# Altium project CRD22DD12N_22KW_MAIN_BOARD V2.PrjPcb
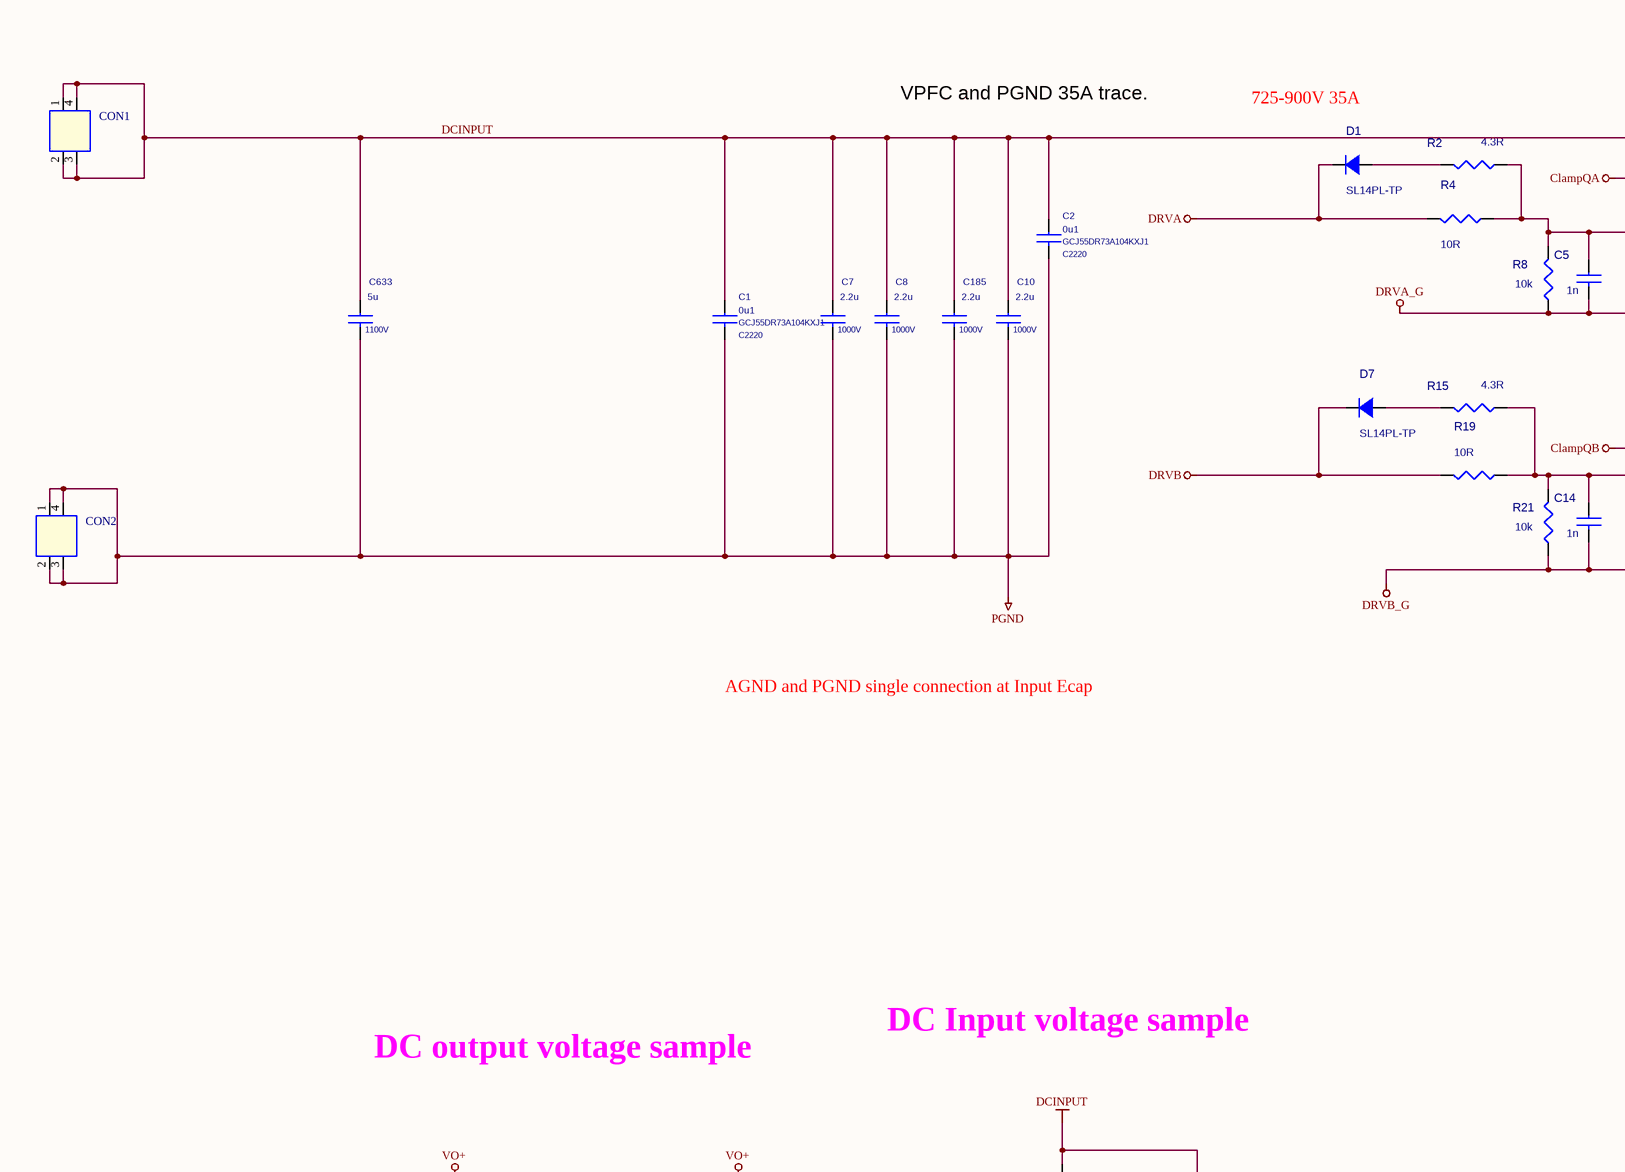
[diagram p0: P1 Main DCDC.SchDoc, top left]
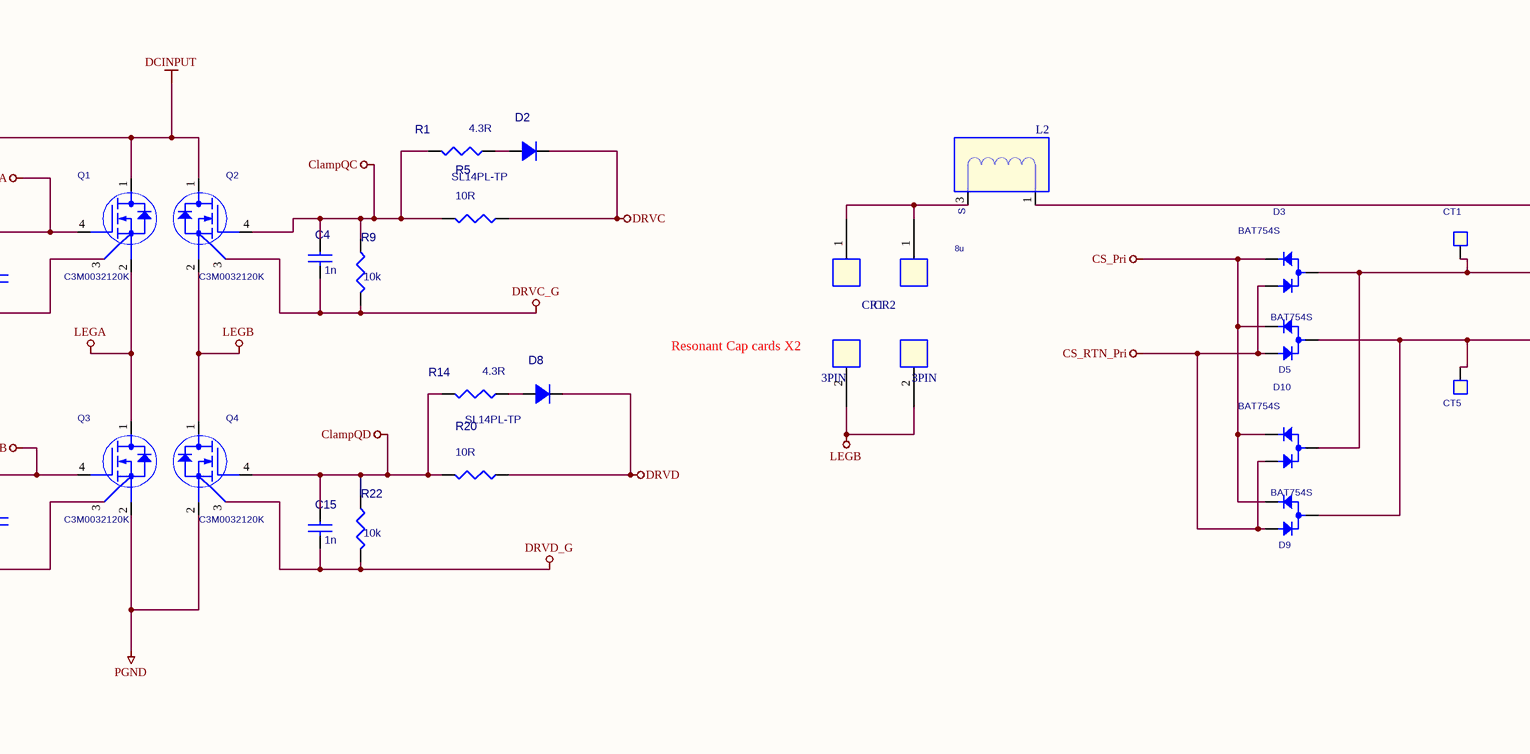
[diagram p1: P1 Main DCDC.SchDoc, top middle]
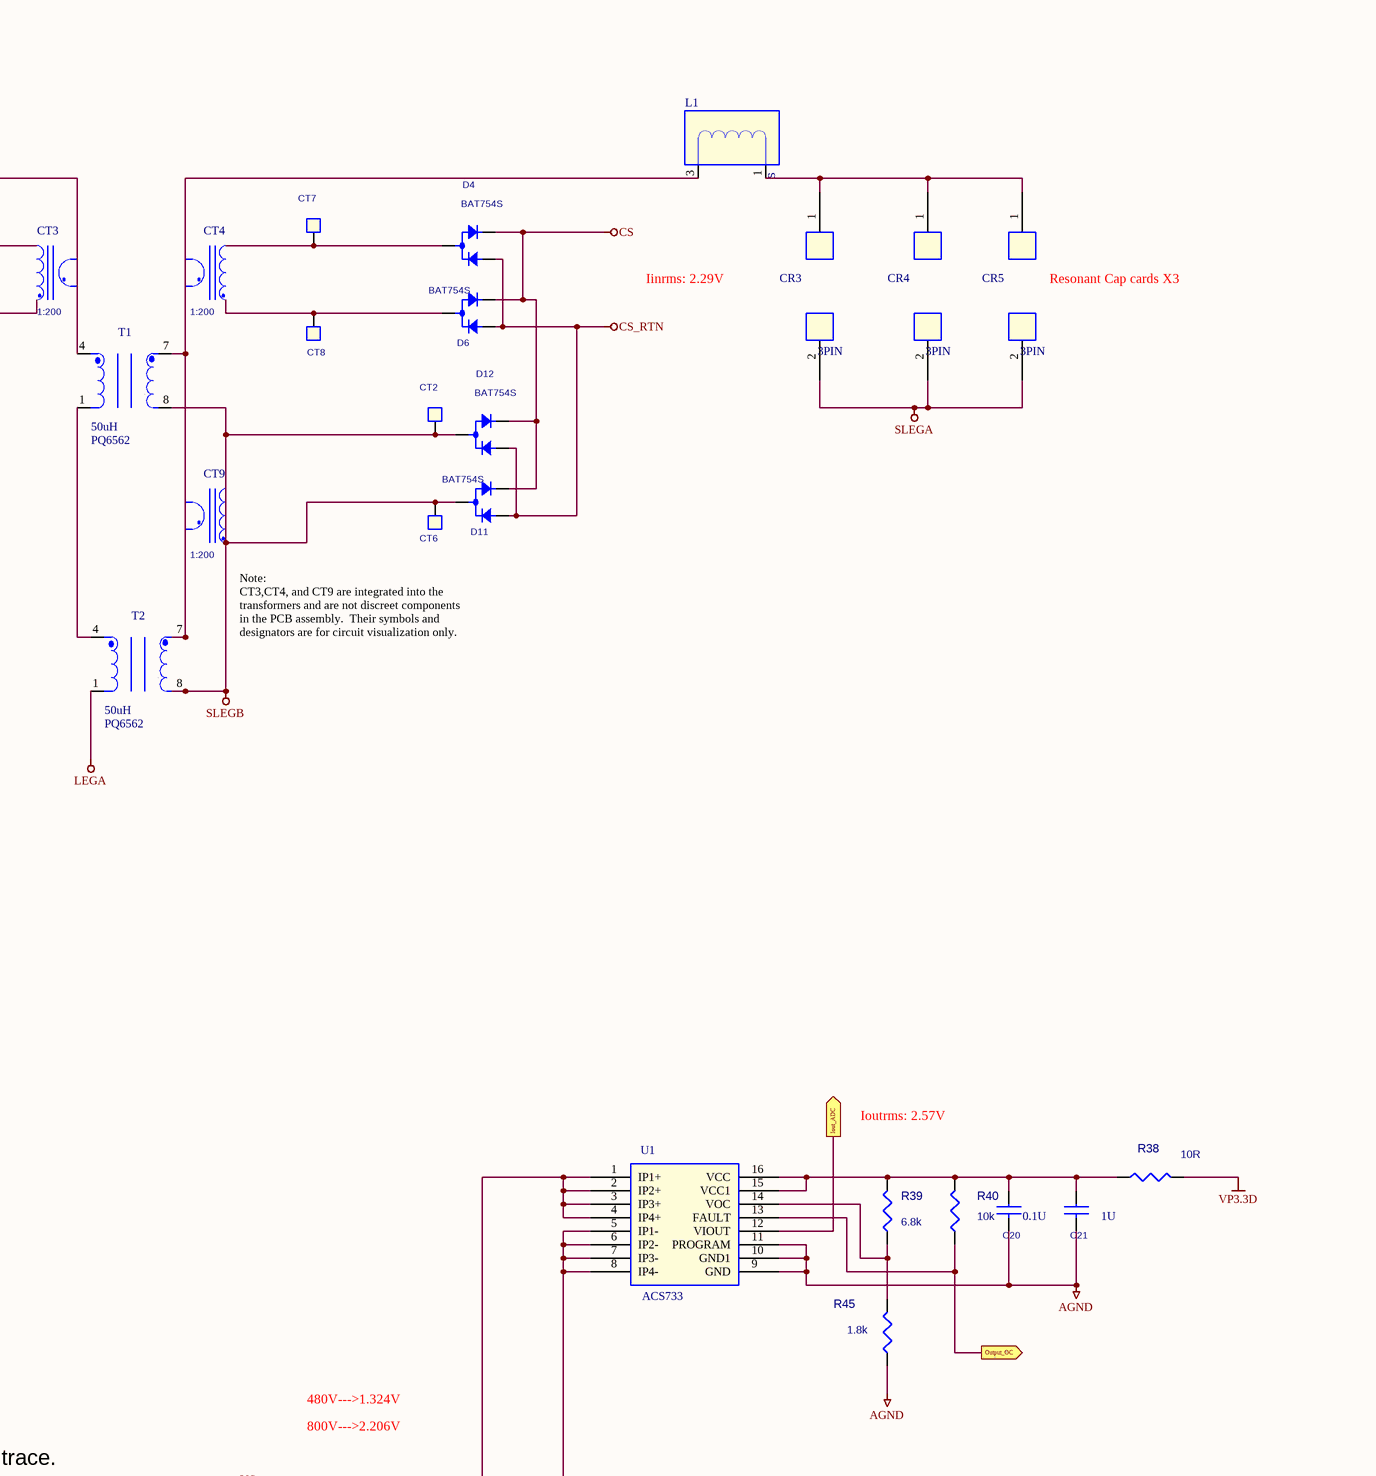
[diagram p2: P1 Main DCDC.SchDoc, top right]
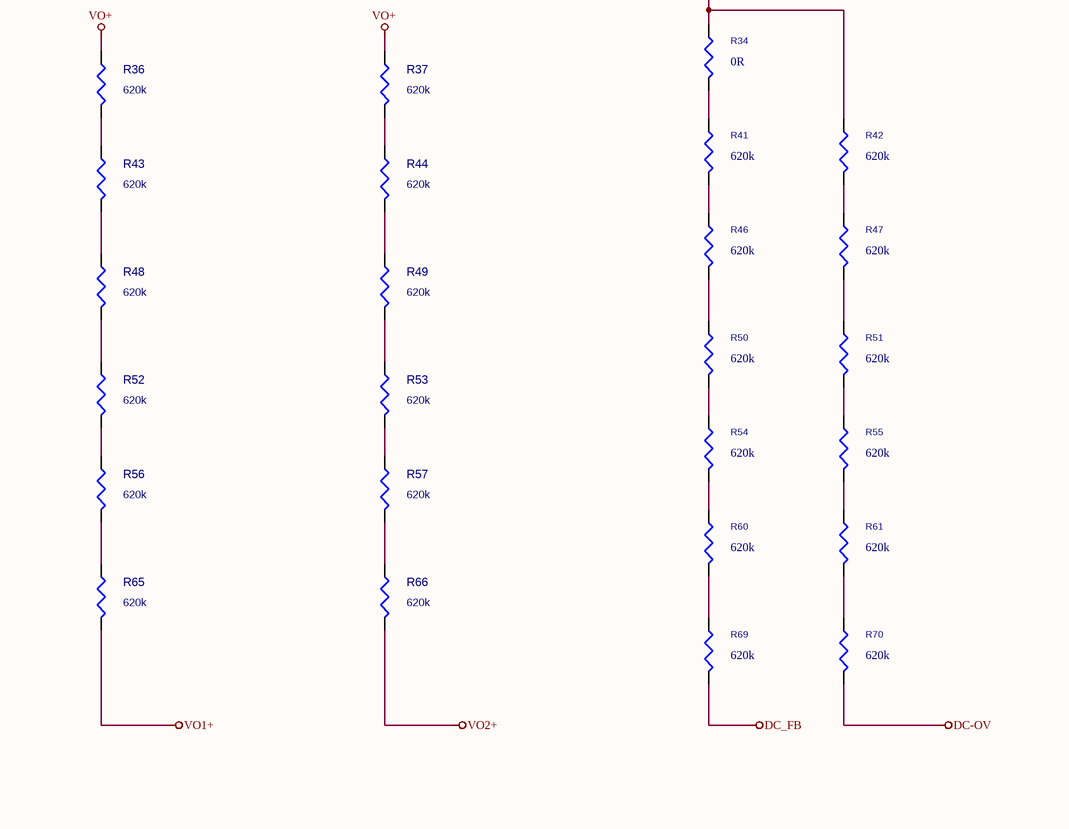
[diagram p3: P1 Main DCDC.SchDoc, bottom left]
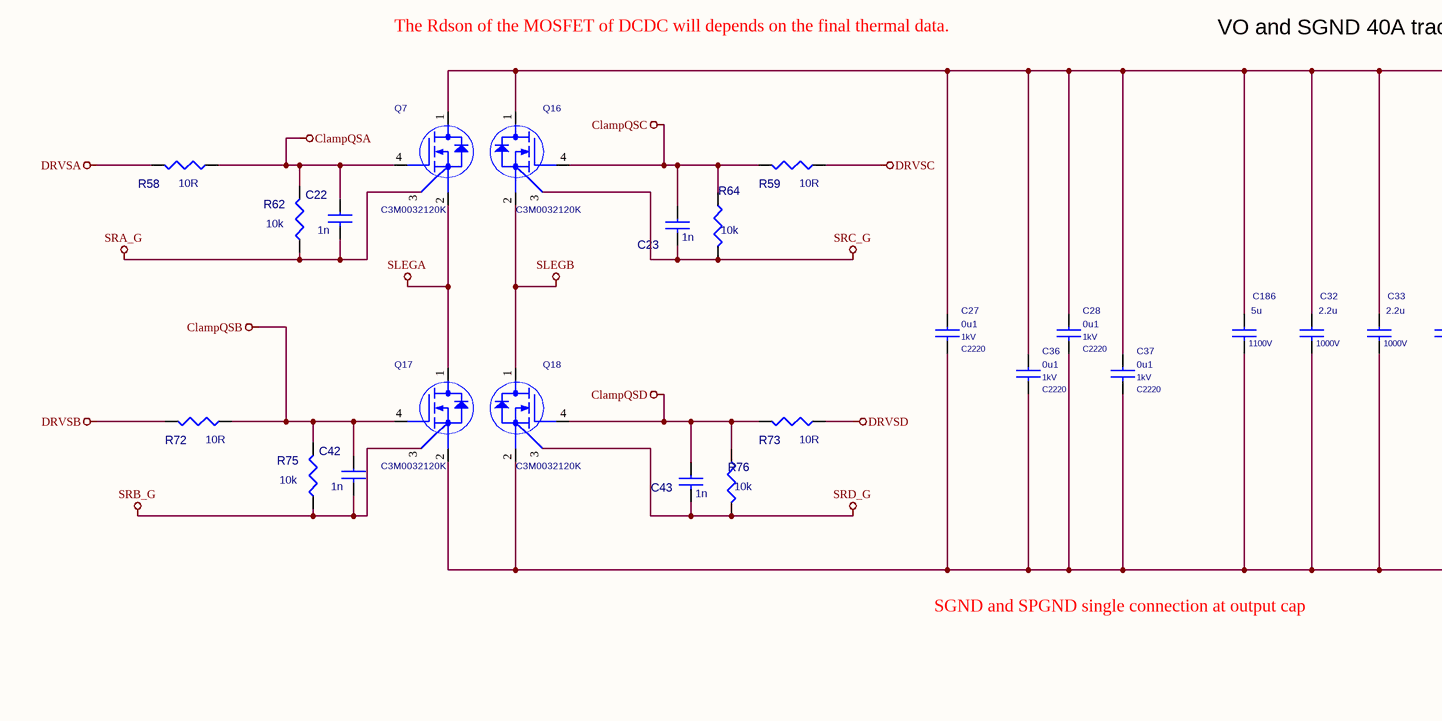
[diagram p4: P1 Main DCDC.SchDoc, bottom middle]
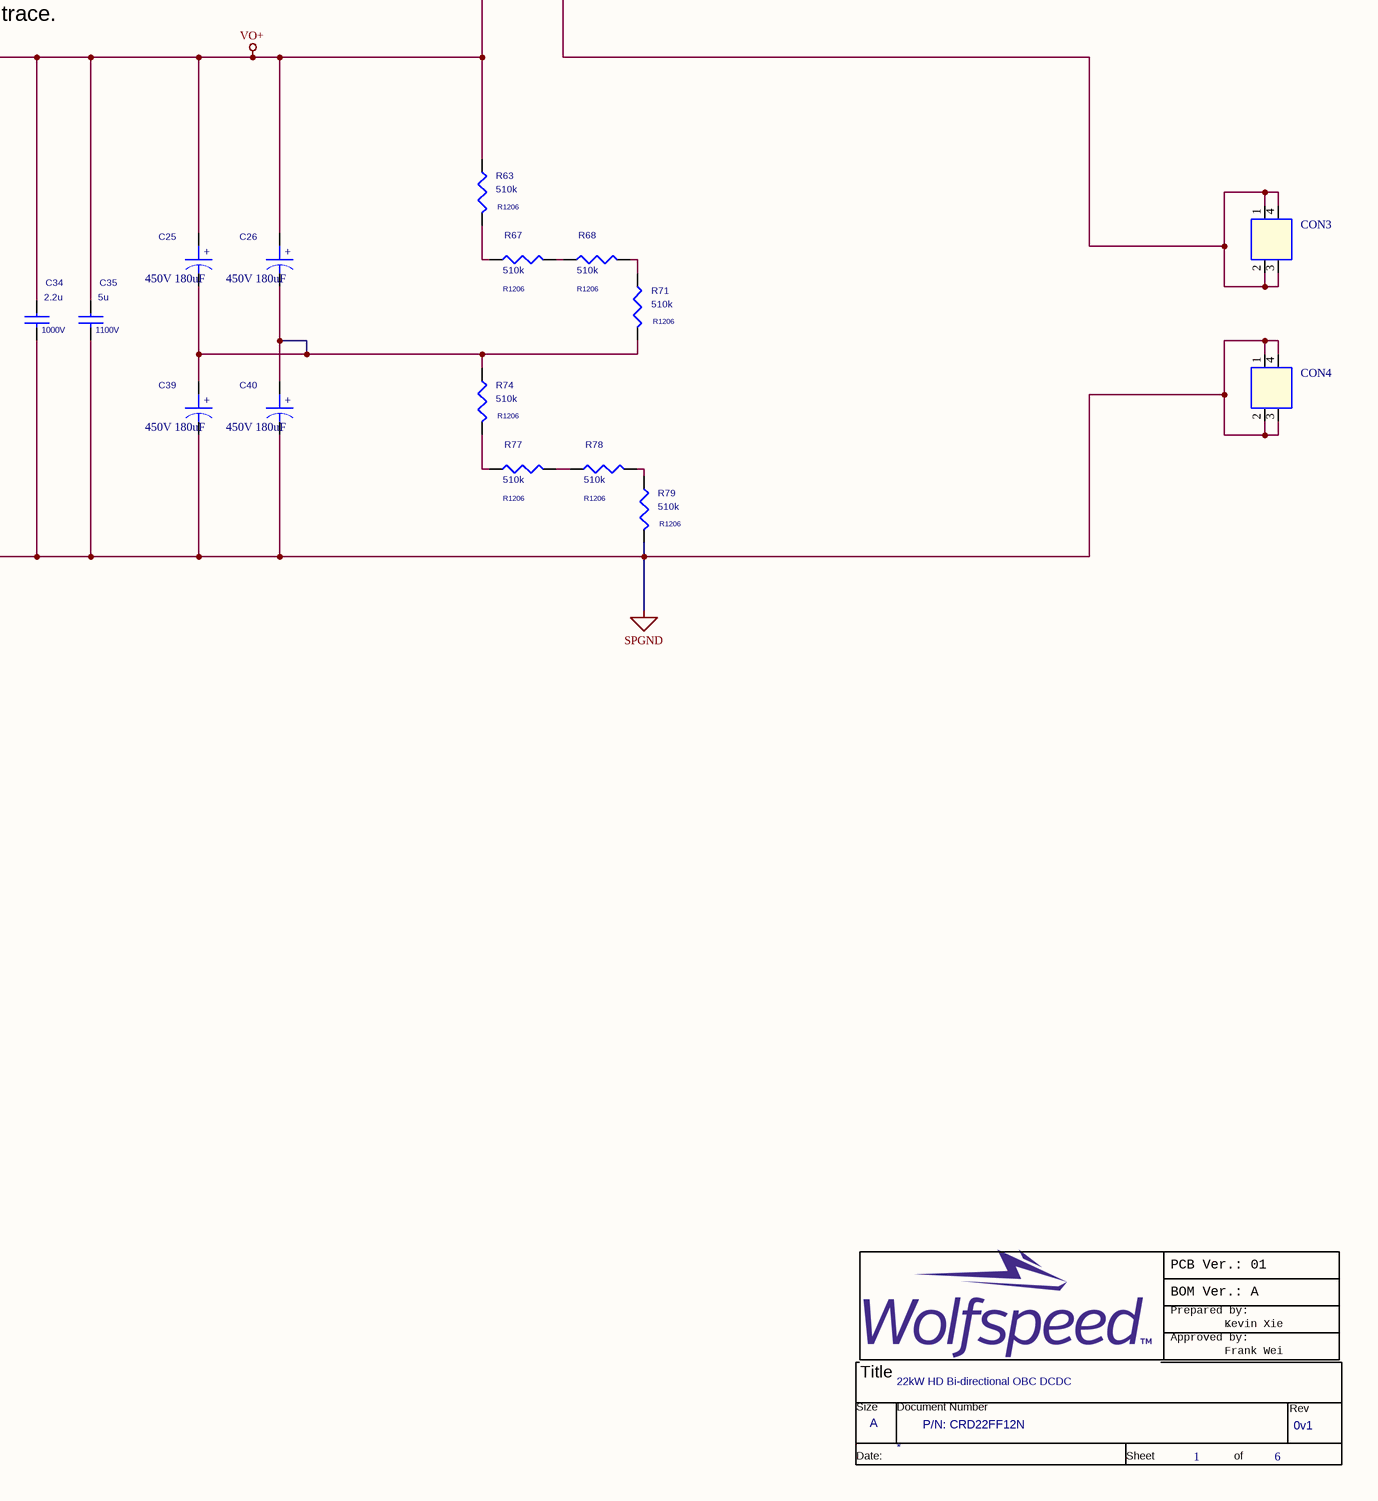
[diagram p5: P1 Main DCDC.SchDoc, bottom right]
5 sheets, 347 parts. Net scope: flat (ports and power ports of the same name join across sheets).
Board file: CRD22DD12N_22KW_BI-OBC_main_BOARD_DCDC_V2.PcbDoc
Sheets:
  P1 Main DCDC.SchDoc
  P2 Bias POWER SUPPLY.SchDoc
  P3 Isolation Interface.SchDoc
  P4 DCDC Primary Gate Dr.SchDoc
  P5 DCDC Secondary Gate .SchDoc

## Sheet P1 Main DCDC.SchDoc
size 840 x 594 mm

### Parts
(Parts that share a designator on the sheet are numbered #1, #2 ... from top to bottom, then left to right.)
*#1  Page Count: 6  Page Number: 1  Page Size: A  Title: 22kW HD Bi-directional OBC DCDC  RevCode: 0v1  Doc: P/N: CRD22FF12N  (hidden comment: TitleBlock0_cree_power)  (graphical)
C1  0u1  value1: GCJ55DR73A104KXJ1  [C2220]
C2  0u1  value1: GCJ55DR73A104KXJ1  [C2220]
C4  1n  [C0603]
C5  1n  [C0603]
C7  2.2u  value1: 1000V  [capfilm_31_5x12_5mm]
C8  2.2u  value1: 1000V  [capfilm_31_5x12_5mm]
C10  2.2u  value1: 1000V  [capfilm_31_5x12_5mm]
C14  1n  [C0603]
C15  1n  [C0603]
C20  0.1U  [C0603]
C21  1U  [C0603]
C22  1n  [C0603]
C23  1n  [C0603]
C25  450V 180uF  [ecap_d18p7_5]
C26  450V 180uF  [ecap_d18p7_5]
C27  0u1  value1: 1kV  [C2220]
C28  0u1  value1: 1kV  [C2220]
C32  2.2u  value1: 1000V  [capfilm_31_5x12_5mm]
C33  2.2u  value1: 1000V  [capfilm_31_5x12_5mm]
C34  2.2u  value1: 1000V  [capfilm_31_5x12_5mm]
C35  5u  value1: 1100V  [capfilm_31_5x18_5mm]
C36  0u1  value1: 1kV  [C2220]
C37  0u1  value1: 1kV  [C2220]
C39  450V 180uF  [ecap_d18p7_5]
C40  450V 180uF  [ecap_d18p7_5]
C42  1n  [C0603]
C43  1n  [C0603]
C185  2.2u  value1: 1000V  [capfilm_31_5x12_5mm]
C186  5u  value1: 1100V  [capfilm_31_5x18_5mm]
C633  5u  value1: 1100V  [capfilm_31_5x18_5mm]
CON1  Connecter  [thread4_9p9x5_1110x920]  (value not drawn)
CON2  Connecter  [thread4_9p9x5_1110x920]  (value not drawn)
CON3  Connecter  [thread4_9p9x5_1110x920]  (value not drawn)
CON4  Connecter  [thread4_9p9x5_1110x920]  (value not drawn)
CR1  3PIN  [Crb]
CR2  3PIN  [Crb]
CR3  3PIN  [Crb]
CR4  3PIN  [Crb]
CR5  3PIN  [Crb]
CT1  T1T2  [TH47_CR98]  (value not drawn)
CT2  T1T2  [TH47_CR98]  (value not drawn)
CT3  1:200  [NO]
CT4  1:200  [NO]
CT5  T1T2  [TH47_CR98]  (value not drawn)
CT6  T1T2  [TH47_CR98]  (value not drawn)
CT7  T1T2  [TH47_CR98]  (value not drawn)
CT8  T1T2  [TH47_CR98]  (value not drawn)
CT9  1:200  [NO]
D1  SL14PL-TP  [SOD-123]
D2  SL14PL-TP  [SOD-123]
D3  BAT754S  [SOT-23]
D4  BAT754S  [SOT-23]
D5  BAT754S  [SOT-23]
D6  BAT754S  [SOT-23]
D7  SL14PL-TP  [SOD-123]
D8  SL14PL-TP  [SOD-123]
D9  BAT754S  [SOT-23]
D10  BAT754S  [SOT-23]
D11  BAT754S  [SOT-23]
D12  BAT754S  [SOT-23]
L1  8u  [l6]  (value not drawn)
L2  8u  [l6]
Q1  C3M0032120K  [to-247-4l]
Q2  C3M0032120K  [to-247-4l]
Q3  C3M0032120K  [to-247-4l]
Q4  C3M0032120K  [to-247-4l]
Q7  C3M0032120K  [to-247-4l]
Q16  C3M0032120K  [to-247-4l]
Q17  C3M0032120K  [to-247-4l]
Q18  C3M0032120K  [to-247-4l]
R1  4.3R  [R1206]
R2  4.3R  [R1206]
R4  10R  [R1206]
R5  10R  [R1206]
R8  10k  [R0603]
R9  10k  [R0603]
R14  4.3R  [R1206]
R15  4.3R  [R1206]
R19  10R  [R1206]
R20  10R  [R1206]
R21  10k  [R0603]
R22  10k  [R0603]
R34  0R  [R1206]
R36  620k  [R1206]
R37  620k  [R1206]
R38  10R  [R0603]
R39  6.8k  [R0603]
R40  10k  [R0603]
R41  620k  [R1206]
R42  620k  [R1206]
R43  620k  [R1206]
R44  620k  [R1206]
R45  1.8k  [R0603]
R46  620k  [R1206]
R47  620k  [R1206]
R48  620k  [R1206]
R49  620k  [R1206]
R50  620k  [R1206]
R51  620k  [R1206]
R52  620k  [R1206]
R53  620k  [R1206]
R54  620k  [R1206]
R55  620k  [R1206]
R56  620k  [R1206]
R57  620k  [R1206]
R58  10R  [R1206]
R59  10R  [R1206]
R60  620k  [R1206]
R61  620k  [R1206]
R62  10k  [R0603]
R63  510k  [R1206]
R64  10k  [R0603]
R65  620k  [R1206]
R66  620k  [R1206]
R67  510k  [R1206]
R68  510k  [R1206]
R69  620k  [R1206]
R70  620k  [R1206]
R71  510k  [R1206]
R72  10R  [R1206]
R73  10R  [R1206]
R74  510k  [R1206]
R75  10k  [R0603]
R76  10k  [R0603]
R77  510k  [R1206]
R78  510k  [R1206]
R79  510k  [R1206]
T1  50uH  LLF Part Number: PQ6562  [IND-LET0234-34x17]
T2  50uH  LLF Part Number: PQ6562  [IND-LET0234-34x17]
U1  ACS733  [SOICW-16]

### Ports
Iout_ADC (out), Output_OC (out)

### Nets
AGND: C20.2 C21.2 R45.2 U1.9(GND) U1.10(GND1) U1.11(PROGRAM)
ClampQA: C5.1 Q1.4(G) R2.1 R4.1 R8.2
ClampQB: C14.1 Q3.4(G) R15.1 R19.1 R21.2
ClampQC: C4.1 Q2.4(G) R1.2 R5.2 R9.2
ClampQD: C15.1 Q4.4(G) R14.2 R20.2 R22.2
ClampQSA: C22.1 Q7.4(G) R58.1 R62.2
ClampQSB: C42.1 Q17.4(G) R72.1 R75.2
ClampQSC: C23.1 Q16.4(G) R59.2 R64.2
ClampQSD: C43.1 Q18.4(G) R73.2 R76.2
CS: D4.2(C2) D6.2(C2) D11.2(C2) D12.2(C2)
CS_Pri: D3.2(C2) D5.2(C2) D9.2(C2) D10.2(C2)
CS_RTN: D4.1(C1) D6.1(C1) D11.1(C1) D12.1(C1)
CS_RTN_Pri: D3.1(C1) D5.1(C1) D9.1(C1) D10.1(C1)
DC-OV: R70.1
DC_FB: R69.1
DCINPUT: C1.1 C2.1 C7.1 C8.1 C10.1 C185.1 C633.1 CON1.1 CON1.2 CON1.3 CON1.4 Q1.1(D) Q2.1(D) R34.2 R42.2
DRVA: D1.2(K) R4.2
DRVA_G: C5.2 Q1.3(GS) R8.1
DRVB: D7.2(K) R19.2
DRVB_G: C14.2 Q3.3(GS) R21.1
DRVC: D2.2(K) R5.1
DRVC_G: C4.2 Q2.3(GS) R9.1
DRVD: D8.2(K) R20.1
DRVD_G: C15.2 Q4.3(GS) R22.1
DRVSA: R58.2
DRVSB: R72.2
DRVSC: R59.1
DRVSD: R73.1
LEGA: Q1.2(S) Q3.1(D) T2.1
LEGB: CR1.2 CR2.2 Q2.2(S) Q4.1(D)
PGND: C1.2 C2.2 C7.2 C8.2 C10.2 C185.2 C633.2 CON2.1 CON2.2 CON2.3 CON2.4 Q3.2(S) Q4.2(S)
SLEGA: CR3.2 CR4.2 CR5.2 Q7.2(S) Q17.1(D)
SLEGB: CT2.1 CT6.1 D11.3(A) D12.3(A) Q16.2(S) Q18.1(D) T1.8 T2.8
SPGND: C27.2 C28.2 C32.2 C33.2 C34.2 C35.2 C36.2 C37.2 C39.2 C40.2 C186.2 CON4.1 CON4.2 CON4.3 CON4.4 Q17.2(S) Q18.2(S) R79.2
SRA_G: C22.2 Q7.3(GS) R62.1
SRB_G: C42.2 Q17.3(GS) R75.1
SRC_G: C23.2 Q16.3(GS) R64.1
SRD_G: C43.2 Q18.3(GS) R76.1
VO1+: R65.2
VO2+: R66.2
VO+: C25.1 C26.1 C27.1 C28.1 C32.1 C33.1 C34.1 C35.1 C36.1 C37.1 C186.1 Q7.1(D) Q16.1(D) R36.1 R37.1 R63.1 U1.1(IP1+) U1.2(IP2+) U1.3(IP3+) U1.4(IP4+)
VP3.3D: R38.1
NetC20_1: C20.1 C21.1 R38.2 R39.1 R40.1 U1.15(VCC1) U1.16(VCC)
NetC25_2: C25.2 C26.2 C39.1 C40.1 R71.2 R74.1
NetCON3_1: CON3.1 CON3.2 CON3.3 CON3.4 U1.5(IP1-) U1.6(IP2-) U1.7(IP3-) U1.8(IP4-)
NetCR1_1: CR1.1 CR2.1 L2.3
NetCR3_1: CR3.1 CR4.1 CR5.1 L1.1
NetCT1_1: CT1.1 D3.3(A) D10.3(A)
NetCT5_1: CT5.1 D5.3(A) D9.3(A)
NetCT7_1: CT7.1 D4.3(A)
NetCT8_1: CT8.1 D6.3(A)
NetD1_1: D1.1(A) R2.2
NetD2_1: D2.1(A) R1.1
NetD7_1: D7.1(A) R15.2
NetD8_1: D8.1(A) R14.1
NetJ1_14: U1.12(VIOUT) ; port Iout_ADC
NetJ1_16: R40.2 U1.13(FAULT) ; port Output_OC
NetL1_3: L1.3 T1.7 T2.7
NetL2_1: L2.1 T1.4
NetR34_1: R34.1 R41.2
NetR36_2: R36.2 R43.1
NetR37_2: R37.2 R44.1
NetR39_2: R39.2 R45.1 U1.14(VOC)
NetR41_1: R41.1 R46.2
NetR42_1: R42.1 R47.2
NetR43_2: R43.2 R48.1
NetR44_2: R44.2 R49.1
NetR46_1: R46.1 R50.2
NetR47_1: R47.1 R51.2
NetR48_2: R48.2 R52.1
NetR49_2: R49.2 R53.1
NetR50_1: R50.1 R54.2
NetR51_1: R51.1 R55.2
NetR52_2: R52.2 R56.1
NetR53_2: R53.2 R57.1
NetR54_1: R54.1 R60.2
NetR55_1: R55.1 R61.2
NetR56_2: R56.2 R65.1
NetR57_2: R57.2 R66.1
NetR60_1: R60.1 R69.2
NetR61_1: R61.1 R70.2
NetR63_2: R63.2 R67.1
NetR67_2: R67.2 R68.1
NetR68_2: R68.2 R71.1
NetR74_2: R74.2 R77.1
NetR77_2: R77.2 R78.1
NetR78_2: R78.2 R79.1
NetT1_1: T1.1 T2.4

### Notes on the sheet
- VPFC and PGND 35A trace.
- 725-900V 35A
- Iinrms: 2.29V
- (near CR5) Resonant Cap cards X3
- (near CR1) Resonant Cap cards X2
- AGND and PGND single connection at Input Ecap
- (near CT9) Note:
  CT3,CT4, and CT9 are integrated into the transformers and are not discreet components in the PCB assembly.  Their symbols and designators are for circuit visualization only.
- DC output voltage sample
- DC Input voltage sample
- Ioutrms: 2.57V
- The Rdson of the MOSFET of DCDC will depends on the final thermal data.
- 480V--->1.324V
- 800V--->2.206V
- VO and SGND 40A trace.
- SGND and SPGND single connection at output cap
- PCB Ver.: 01
- BOM Ver.: A
- Prepared by:
- Approved by:
- .
- Frank Wei
- Kevin Xie

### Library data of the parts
C1 C2 C4 C5 C7 C8 C10 C14 C15 C22 C23 C27 C28 C32-C37 C42 C43 C185 C186 C633 = CAP NP_Dup1
C20 C21 = CAP NP
C25 C26 C39 C40 = CAP POL
CT1 CT2 CT5-CT8 = CON1_2
CT3 CT4 CT9 = TRNSFMR 29398_4
D1 D2 D7 D8 = DIODE_0
D3-D6 D9-D12 = FMMD6100/SOT_0
L1 = 126LNS_1
L2 = 126LNS_5
Q1-Q4 Q7 Q16-Q18 = C3M0065090J_4
R1 R2 R4 R5 R8 R9 R14 R15 R19-R22 R36-R40 R43-R45 R48 R49 R52 R53 R56-R59 R62 R64-R66 R72 R73 R75 R76 = R
R34 R41 R42 R46 R47 R50 R51 R54 R55 R60 R61 R69 R70 = RESISTOR
R63 R67 R68 R71 R74 R77-R79 = RESISTOR_Dup1
T1 = LET0234_326uH_0: PCB Footprint: XFMR-PQ6562_T1
T2 = LET0234_326uH_0: PCB Footprint: XFMR-PQ6562_T2
U1 = MCR1101_0

## Sheet P2 Bias POWER SUPPLY.SchDoc
size 840 x 594 mm
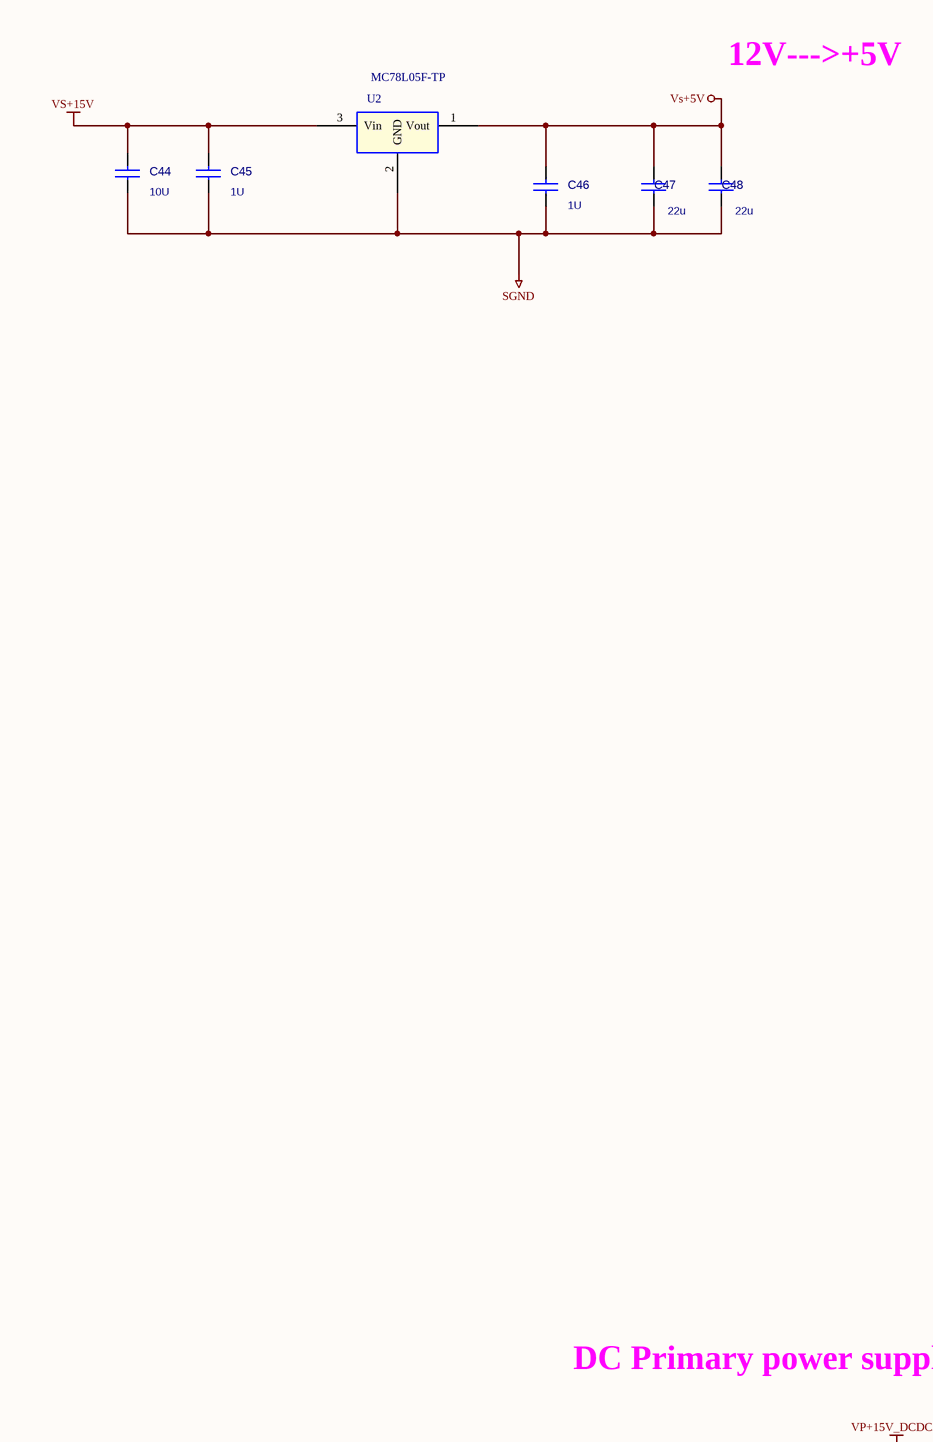
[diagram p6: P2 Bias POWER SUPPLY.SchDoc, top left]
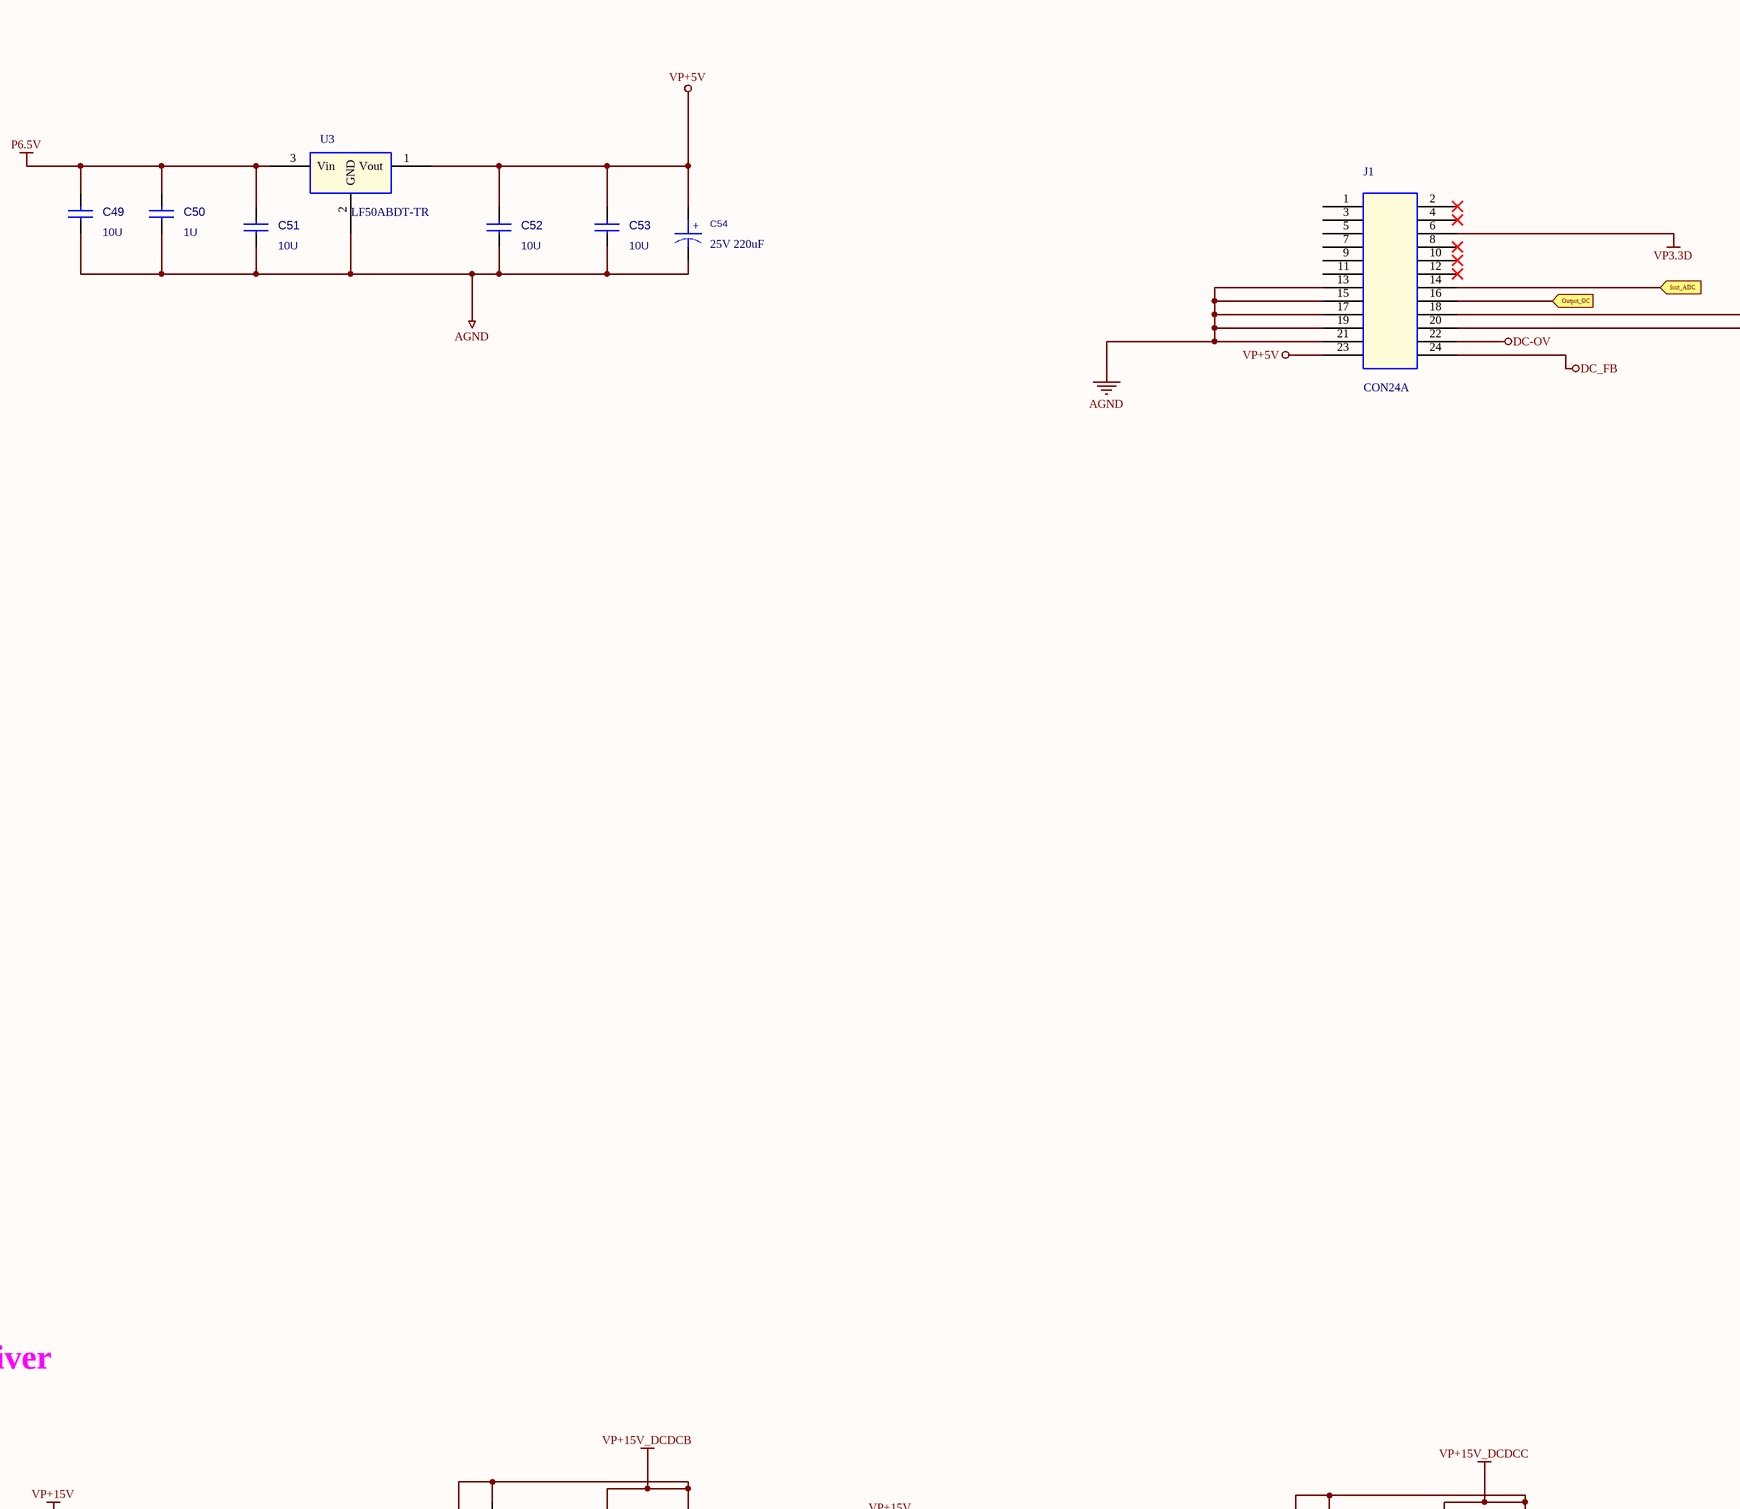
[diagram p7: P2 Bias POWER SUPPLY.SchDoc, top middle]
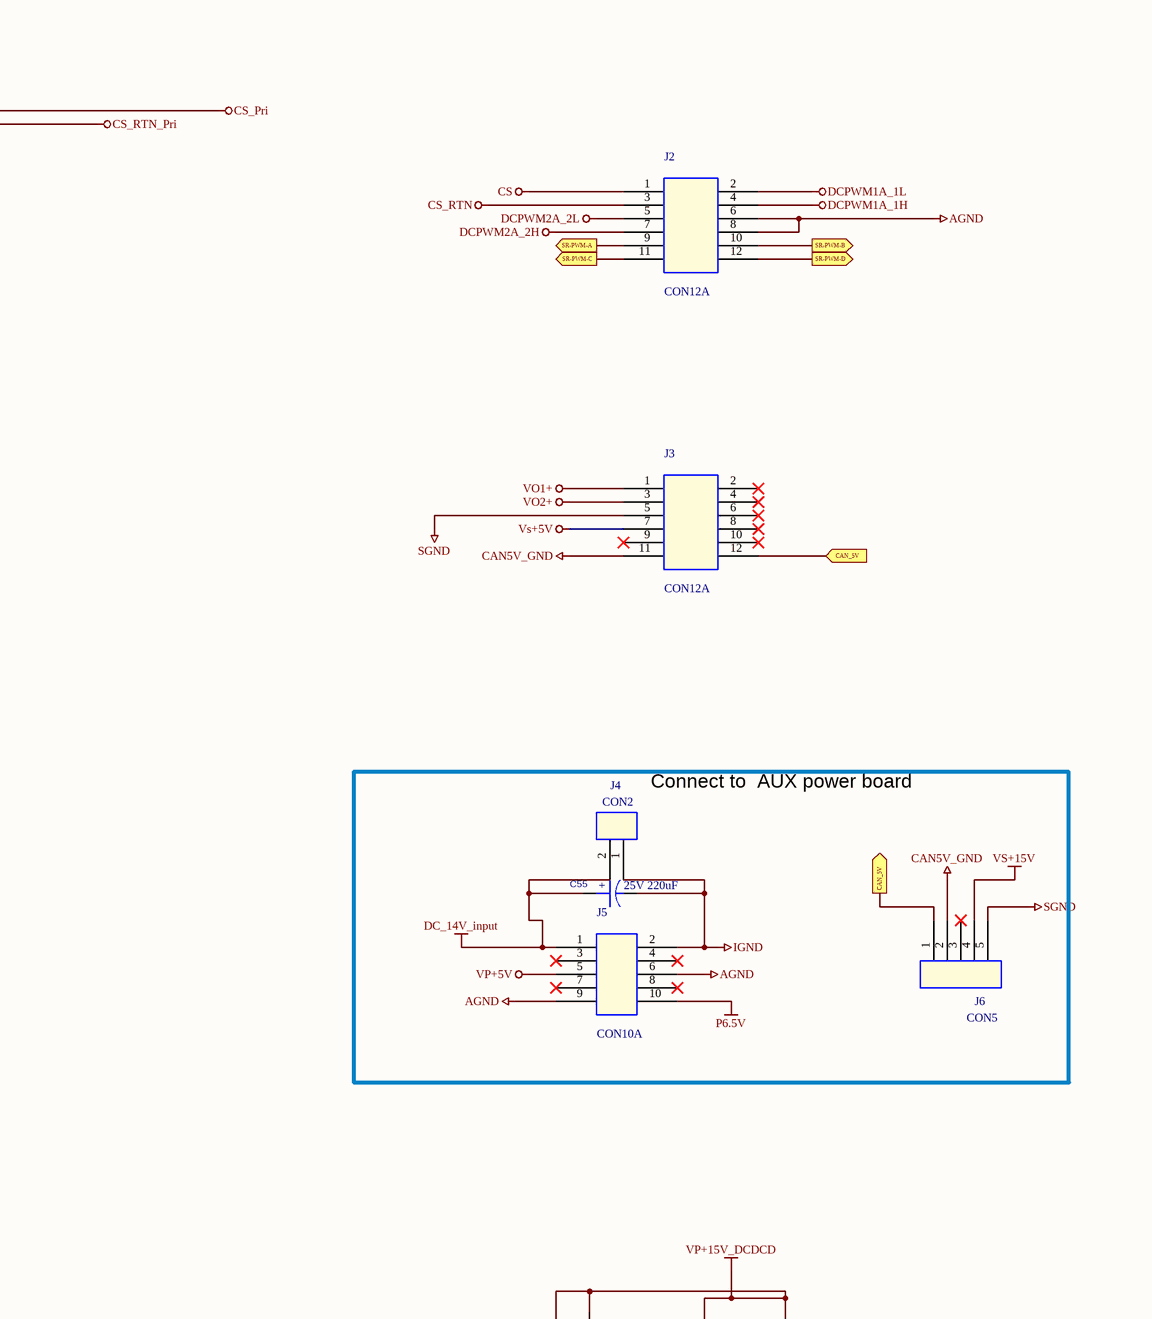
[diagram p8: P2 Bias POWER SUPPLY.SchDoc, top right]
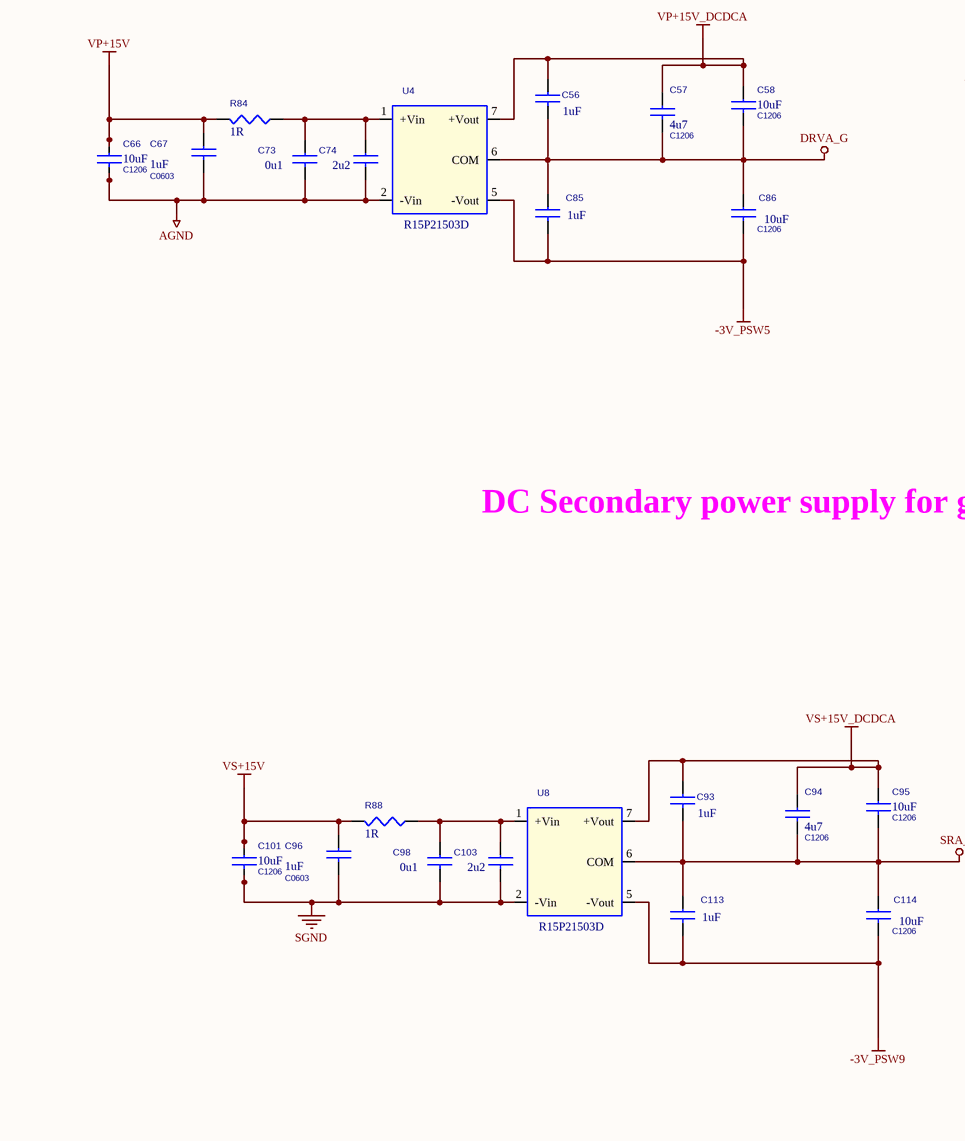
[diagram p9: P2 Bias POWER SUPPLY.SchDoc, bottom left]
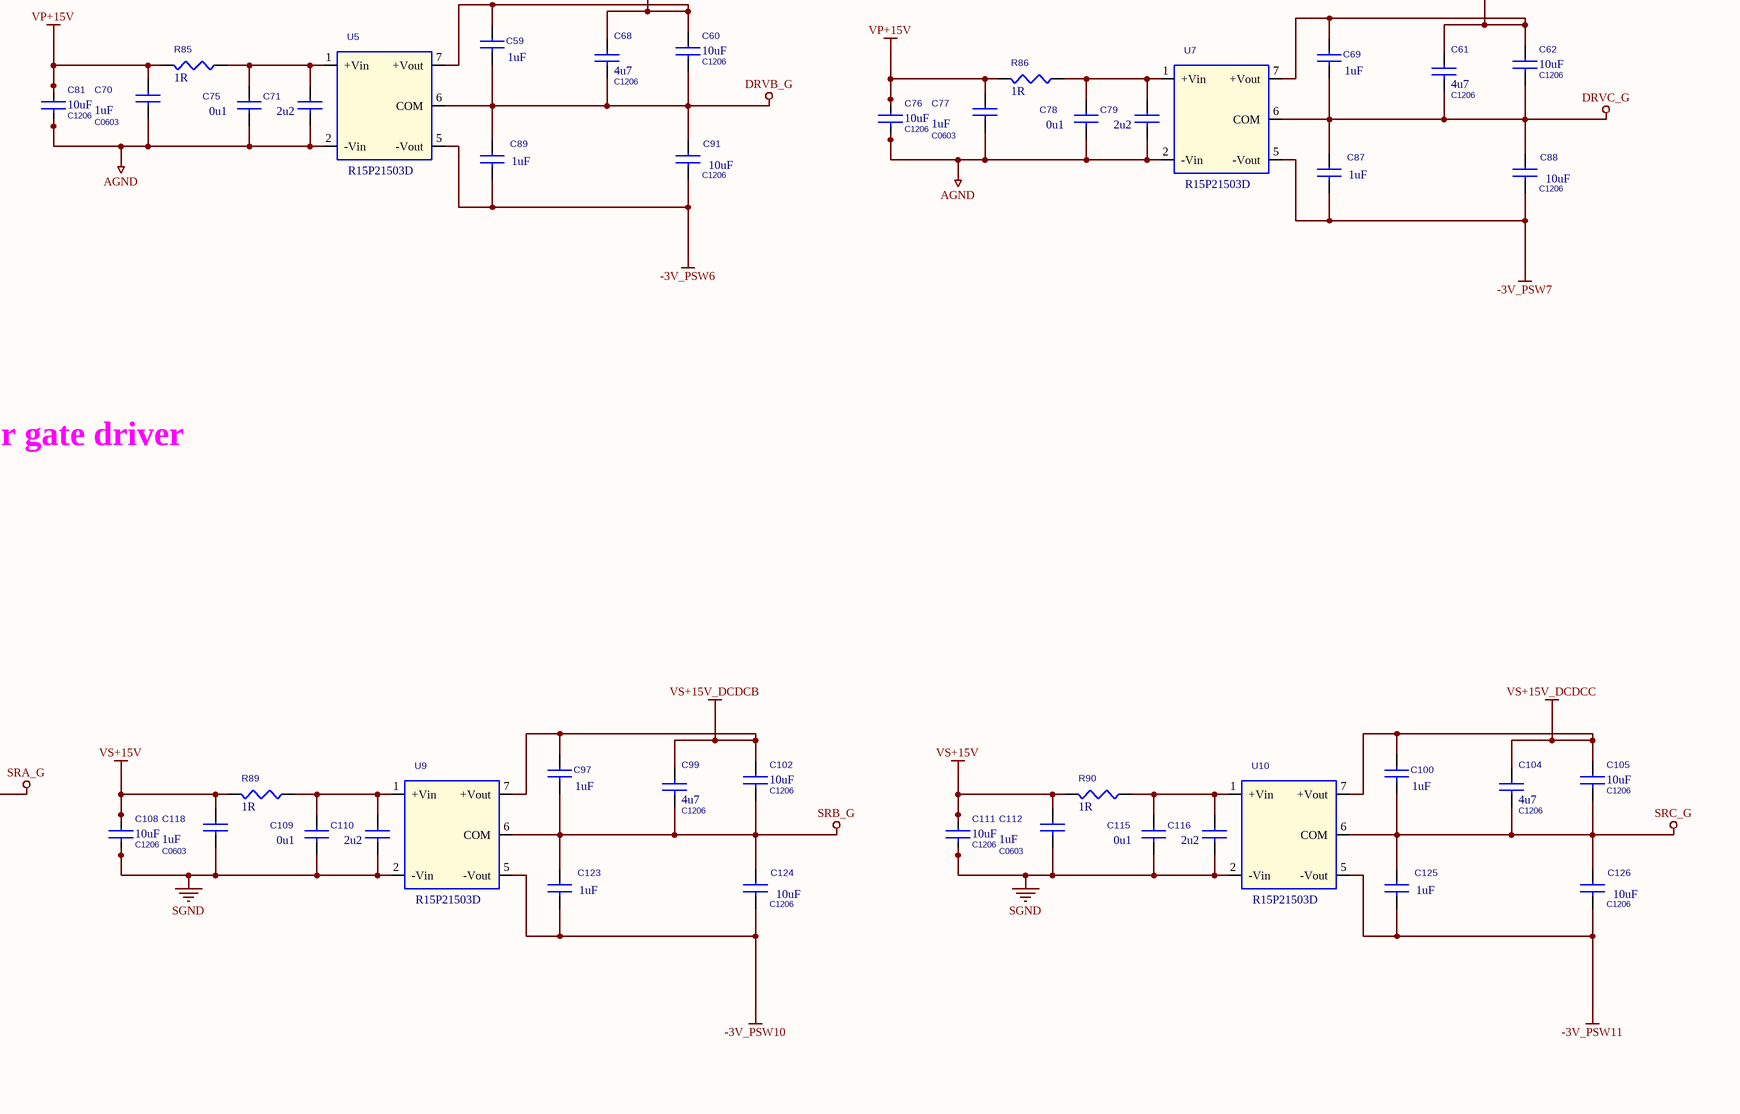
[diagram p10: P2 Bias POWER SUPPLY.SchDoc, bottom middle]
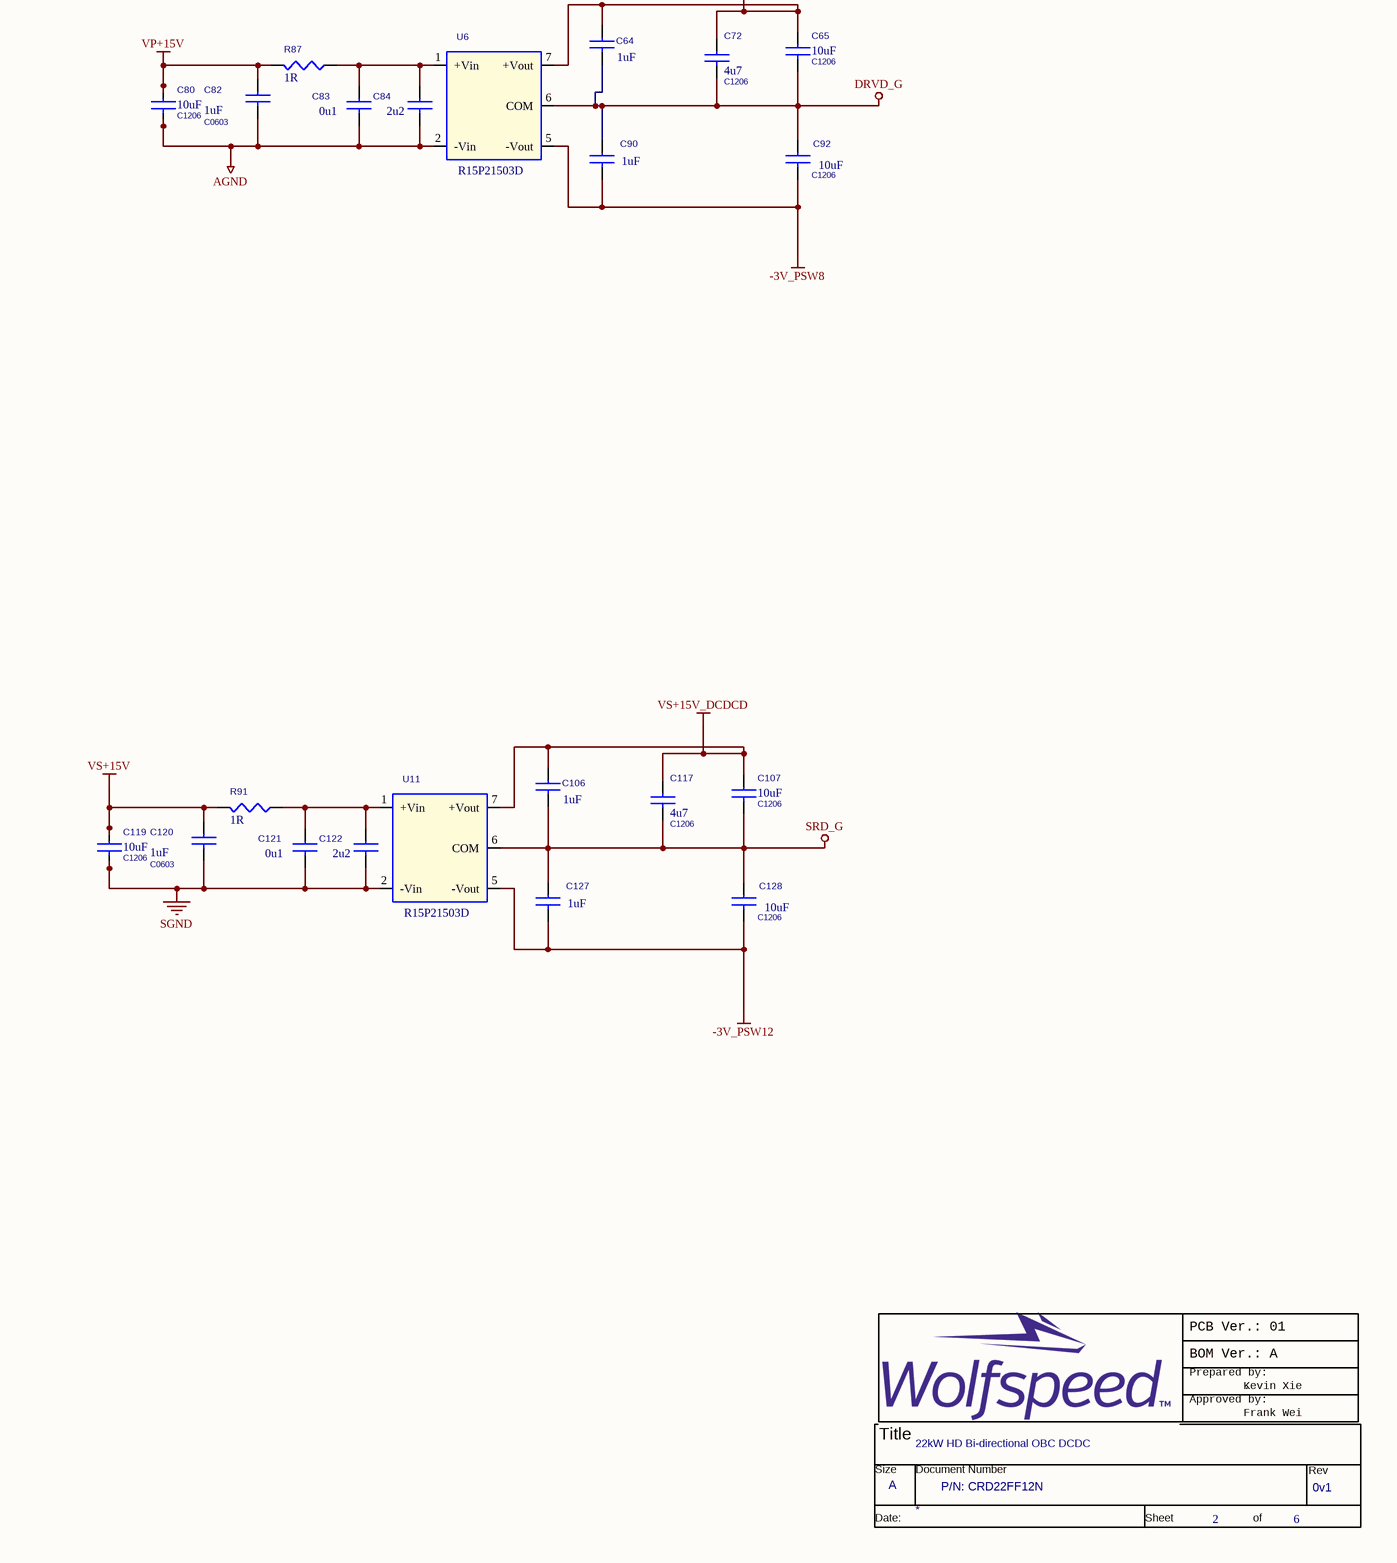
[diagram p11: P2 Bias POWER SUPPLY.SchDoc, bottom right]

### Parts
(Parts that share a designator on the sheet are numbered #1, #2 ... from top to bottom, then left to right.)
*#2  Page Count: 6  Page Number: 2  Page Size: A  Title: 22kW HD Bi-directional OBC DCDC  RevCode: 0v1  Doc: P/N: CRD22FF12N  (hidden comment: TitleBlock0_cree_power)  (graphical)
C44  10U  [C1206]
C45  1U  [C0603]
C46  1U  [C0603]
C47  22u  [C1206]
C48  22u  [C1206]
C49  10U  [C1206]
C50  1U  [C0603]
C51  10U  [C1206]
C52  10U  [C1206]
C53  10U  [C1206]
C54  25V 220uF  [ecap_d8p3_5]
C55  25V 220uF  [ecap_d8p3_5]
C56  1uF  [C0603]
C57  4u7  [C1206]
C58  10uF  [C1206]
C59  1uF  [C0603]
C60  10uF  [C1206]
C61  4u7  [C1206]
C62  10uF  [C1206]
C64  1uF  [C0603]
C65  10uF  [C1206]
C66  10uF  [C1206]
C67  1uF  [C0603]
C68  4u7  [C1206]
C69  1uF  [C0603]
C70  1uF  [C0603]
C71  2u2  [C0805]
C72  4u7  [C1206]
C73  0u1  [C0603]
C74  2u2  [C0805]
C75  0u1  [C0603]
C76  10uF  [C1206]
C77  1uF  [C0603]
C78  0u1  [C0603]
C79  2u2  [C0805]
C80  10uF  [C1206]
C81  10uF  [C1206]
C82  1uF  [C0603]
C83  0u1  [C0603]
C84  2u2  [C0805]
C85  1uF  [C0603]
C86  10uF  [C1206]
C87  1uF  [C0603]
C88  10uF  [C1206]
C89  1uF  [C0603]
C90  1uF  [C0603]
C91  10uF  [C1206]
C92  10uF  [C1206]
C93  1uF  [C0603]
C94  4u7  [C1206]
C95  10uF  [C1206]
C96  1uF  [C0603]
C97  1uF  [C0603]
C98  0u1  [C0603]
C99  4u7  [C1206]
C100  1uF  [C0603]
C101  10uF  [C1206]
C102  10uF  [C1206]
C103  2u2  [C0805]
C104  4u7  [C1206]
C105  10uF  [C1206]
C106  1uF  [C0603]
C107  10uF  [C1206]
C108  10uF  [C1206]
C109  0u1  [C0603]
C110  2u2  [C0805]
C111  10uF  [C1206]
C112  1uF  [C0603]
C113  1uF  [C0603]
C114  10uF  [C1206]
C115  0u1  [C0603]
C116  2u2  [C0805]
C117  4u7  [C1206]
C118  1uF  [C0603]
C119  10uF  [C1206]
C120  1uF  [C0603]
C121  0u1  [C0603]
C122  2u2  [C0805]
C123  1uF  [C0603]
C124  10uF  [C1206]
C125  1uF  [C0603]
C126  10uF  [C1206]
C127  1uF  [C0603]
C128  10uF  [C1206]
J1  CON24A  [con_2mm54_12x2]
J2  CON12A  [con_2mm54_6x2]
J3  CON12A  [con_2mm54_6x2]
J4  CON2  [CON_5MM_2X1]
J5  CON10A  [con_2mm54_5x2]
J6  CON5  [con_2mm54_5x1]
R84  1R  [R0805]
R85  1R  [R0805]
R86  1R  [R0805]
R87  1R  [R0805]
R88  1R  [R0805]
R89  1R  [R0805]
R90  1R  [R0805]
R91  1R  [R0805]
U2  MC78L05F-TP  [SOT-89-3L]
U3  LF50ABDT-TR  [TO252AB]
U4  R15P21503D  [g1212s_2w11]
U5  R15P21503D  [g1212s_2w11]
U6  R15P21503D  [g1212s_2w11]
U7  R15P21503D  [g1212s_2w11]
U8  R15P21503D  [g1212s_2w11]
U9  R15P21503D  [g1212s_2w11]
U10  R15P21503D  [g1212s_2w11]
U11  R15P21503D  [g1212s_2w11]

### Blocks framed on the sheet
Connect to  AUX power board: C55 J4-J6

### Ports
CAN_5V (in), CAN_5V (out), Iout_ADC (in), Output_OC (in), SR-PWM-A (out), SR-PWM-B (out), SR-PWM-C (out), SR-PWM-D (out)

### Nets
-3V_PSW5: C85.2 C86.2 U4.5(-Vout)
-3V_PSW6: C89.2 C91.2 U5.5(-Vout)
-3V_PSW7: C87.2 C88.2 U7.5(-Vout)
-3V_PSW8: C90.2 C92.2 U6.5(-Vout)
-3V_PSW9: C113.2 C114.2 U8.5(-Vout)
-3V_PSW10: C123.2 C124.2 U9.5(-Vout)
-3V_PSW11: C125.2 C126.2 U10.5(-Vout)
-3V_PSW12: C127.2 C128.2 U11.5(-Vout)
AGND: C49.1 C50.1 C51.1 C52.1 C53.1 C54.2 C66.2 C67.2 C70.2 C71.2 C73.2 C74.2 C75.2 C76.2 C77.2 C78.2 C79.2 C80.2 C81.2 C82.2 C83.2 C84.2 J1.13 J1.15 J1.17 J1.19 J1.21 J2.6 J2.8 J5.6 J5.9 U3.2(GND) U4.2(-Vin) U5.2(-Vin) U6.2(-Vin) U7.2(-Vin)
CAN5V_GND: J3.11 J6.2
CS: J2.1
CS_Pri: J1.18
CS_RTN: J2.3
CS_RTN_Pri: J1.20
DC-OV: J1.22
DC_14V_input: C55.1 J4.2 J5.1
DC_FB: J1.24
DCPWM1A_1H: J2.4
DCPWM1A_1L: J2.2
DCPWM2A_2H: J2.7
DCPWM2A_2L: J2.5
DRVA_G: C56.2 C57.2 C58.2 C85.1 C86.1 U4.6(COM)
DRVB_G: C59.2 C60.2 C68.2 C89.1 C91.1 U5.6(COM)
DRVC_G: C61.2 C62.2 C69.2 C87.1 C88.1 U7.6(COM)
DRVD_G: C64.2 C65.2 C72.2 C90.1 C92.1 U6.6(COM)
IGND: C55.2 J4.1 J5.2
P6.5V: C49.2 C50.2 C51.2 J5.10 U3.3(Vin)
SGND: C44.1 C45.1 C46.1 C47.1 C48.1 C96.2 C98.2 C101.2 C103.2 C108.2 C109.2 C110.2 C111.2 C112.2 C115.2 C116.2 C118.2 C119.2 C120.2 C121.2 C122.2 J3.5 J6.5 U2.2(GND) U8.2(-Vin) U9.2(-Vin) U10.2(-Vin) U11.2(-Vin)
SRA_G: C93.2 C94.2 C95.2 C113.1 C114.1 U8.6(COM)
SRB_G: C97.2 C99.2 C102.2 C123.1 C124.1 U9.6(COM)
SRC_G: C100.2 C104.2 C105.2 C125.1 C126.1 U10.6(COM)
SRD_G: C106.2 C107.2 C117.2 C127.1 C128.1 U11.6(COM)
VO1+: J3.1
VO2+: J3.3
VP3.3D: J1.6
VP+5V: C52.2 C53.2 C54.1 J1.23 J5.5 U3.1(Vout)
VP+15V: C66.1 C67.1 C70.1 C76.1 C77.1 C80.1 C81.1 C82.1 R84.2 R85.2 R86.2 R87.2
VP+15V_DCDCA: C56.1 C57.1 C58.1 U4.7(+Vout)
VP+15V_DCDCB: C59.1 C60.1 C68.1 U5.7(+Vout)
VP+15V_DCDCC: C61.1 C62.1 C69.1 U7.7(+Vout)
VP+15V_DCDCD: C64.1 C65.1 C72.1 U6.7(+Vout)
Vs+5V: C46.2 C47.2 C48.2 J3.7 U2.1(Vout)
VS+15V: C44.2 C45.2 C96.1 C101.1 C108.1 C111.1 C112.1 C118.1 C119.1 C120.1 J6.4 R88.2 R89.2 R90.2 R91.2 U2.3(Vin)
VS+15V_DCDCA: C93.1 C94.1 C95.1 U8.7(+Vout)
VS+15V_DCDCB: C97.1 C99.1 C102.1 U9.7(+Vout)
VS+15V_DCDCC: C100.1 C104.1 C105.1 U10.7(+Vout)
VS+15V_DCDCD: C106.1 C107.1 C117.1 U11.7(+Vout)
NetC71_1: C71.1 C75.1 R85.1 U5.1(+Vin)
NetC73_1: C73.1 C74.1 R84.1 U4.1(+Vin)
NetC78_1: C78.1 C79.1 R86.1 U7.1(+Vin)
NetC83_1: C83.1 C84.1 R87.1 U6.1(+Vin)
NetC98_1: C98.1 C103.1 R88.1 U8.1(+Vin)
NetC109_1: C109.1 C110.1 R89.1 U9.1(+Vin)
NetC115_1: C115.1 C116.1 R90.1 U10.1(+Vin)
NetC121_1: C121.1 C122.1 R91.1 U11.1(+Vin)
NetJ1_14: J1.14 ; port Iout_ADC
NetJ1_16: J1.16 ; port Output_OC
NetJ2_9: J2.9 ; port SR-PWM-A
NetJ2_10: J2.10 ; port SR-PWM-B
NetJ2_11: J2.11 ; port SR-PWM-C
NetJ2_12: J2.12 ; port SR-PWM-D
NetJ3_12: J3.12 J6.1 ; port CAN_5V

Not connected (* = marked no-connect by the designer): J1 1 2* 3 4* 5 7 8* 9 10* 11 12*; J3 2* 4* 6* 8* 9* 10*; J5 3* 4* 7* 8*; J6 3*

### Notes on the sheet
- 12V--->+5V
- DC Primary power supply for gate driver
- DC Secondary power supply for gate driver
- PCB Ver.: 01
- BOM Ver.: A
- Prepared by:
- Approved by:
- .
- Frank Wei
- Kevin Xie

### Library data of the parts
C44-C53 = CAP NP_Dup1
C54 C55 = CAP POL
C56-C62 C64-C128 = CAP NP
R84-R91 = RESISTOR
U3 = MC78L05F-TP
U4-U11 = E1212S-2WR2_3

## Sheet P3 Isolation Interface.SchDoc
size 420 x 297 mm
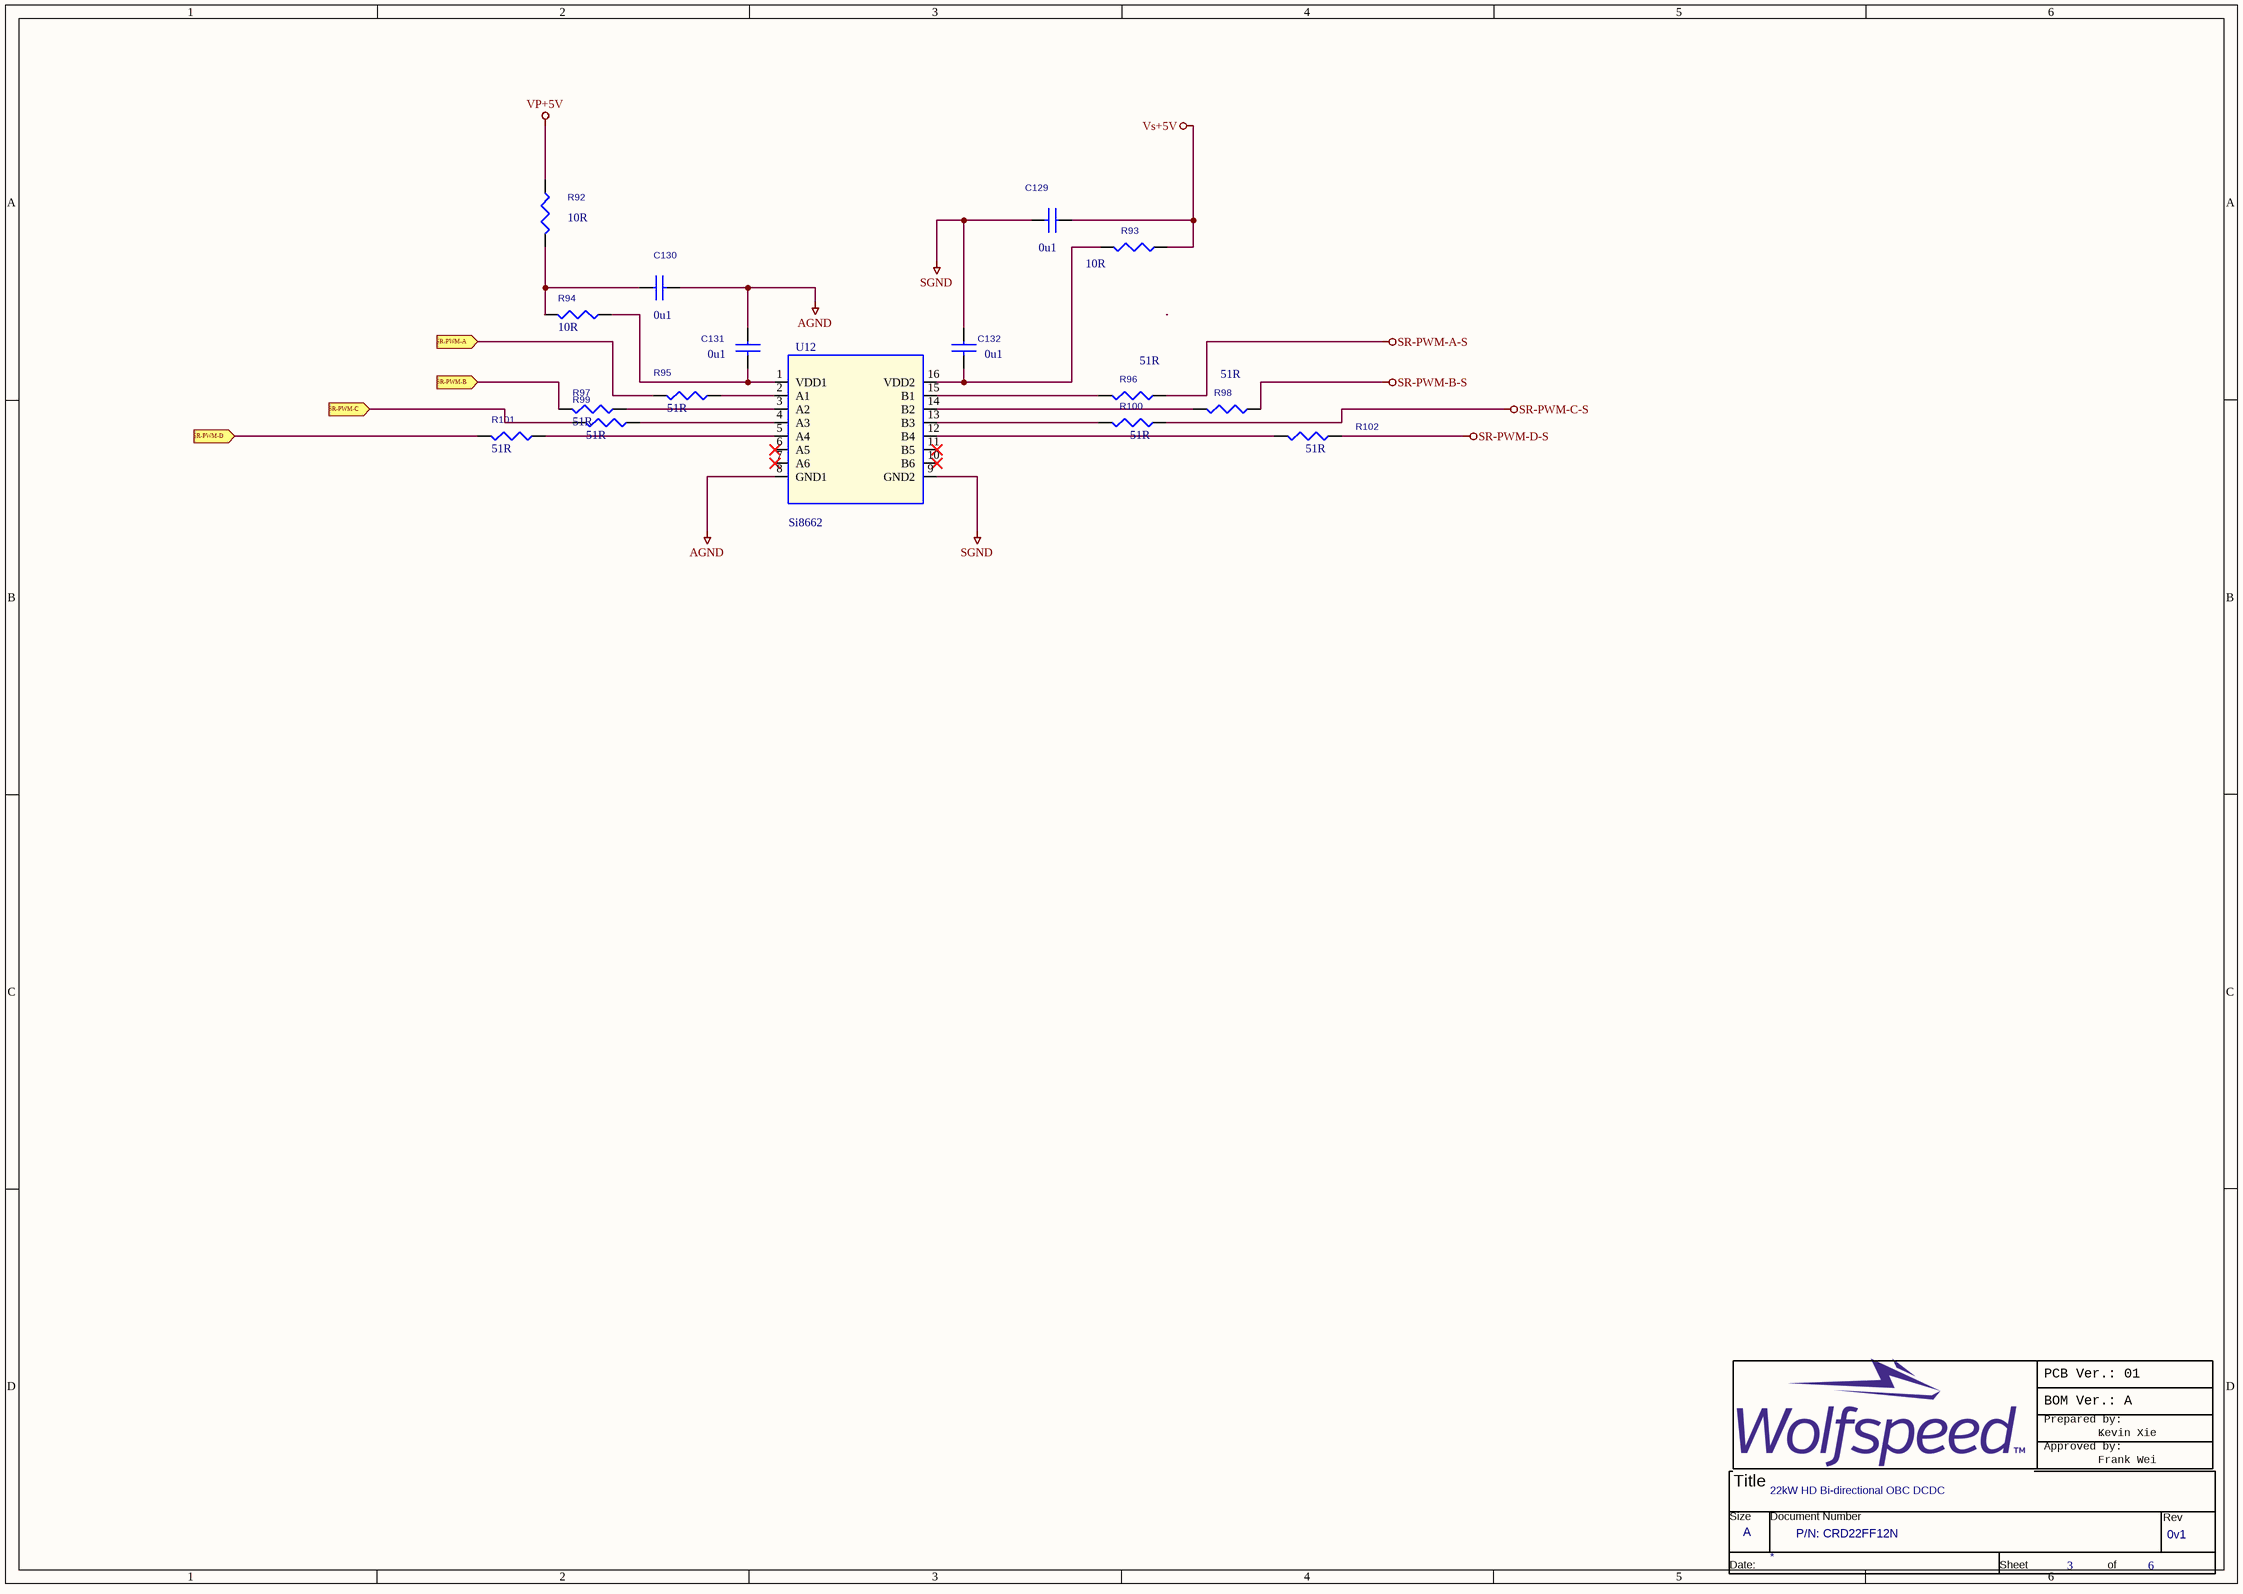
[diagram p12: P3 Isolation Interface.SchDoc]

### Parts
(Parts that share a designator on the sheet are numbered #1, #2 ... from top to bottom, then left to right.)
*#3  Page Count: 6  Page Number: 3  Page Size: A  Title: 22kW HD Bi-directional OBC DCDC  RevCode: 0v1  Doc: P/N: CRD22FF12N  (hidden comment: TitleBlock0_cree_power)  (graphical)
C129  0u1  [C0603]
C130  0u1  [C0603]
C131  0u1  [C0603]
C132  0u1  [C0603]
R92  10R  [R0603]
R93  10R  [R0603]
R94  10R  [R0603]
R95  51R  [R0603]
R96  51R  [R0603]
R97  51R  [R0603]
R98  51R  [R0603]
R99  51R  [R0603]
R100  51R  [R0603]
R101  51R  [R0603]
R102  51R  [R0603]
U12  Si8662  [WB_SOIC16]

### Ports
SR-PWM-A (in), SR-PWM-B (in), SR-PWM-C (in), SR-PWM-D (in)

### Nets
AGND: C130.2 C131.1 U12.8(GND1)
SGND: C129.2 C132.1 U12.9(GND2)
SR-PWM-A-S: R96.2
SR-PWM-B-S: R98.2
SR-PWM-C-S: R100.2
SR-PWM-D-S: R102.2
VP+5V: R92.1
Vs+5V: C129.1 R93.2
NetC130_1: C130.1 R92.2 R94.2
NetC131_2: C131.2 R94.1 U12.1(VDD1)
NetC132_2: C132.2 R93.1 U12.16(VDD2)
NetJ2_9: R95.2 ; port SR-PWM-A
NetJ2_10: R97.2 ; port SR-PWM-B
NetJ2_11: R99.2 ; port SR-PWM-C
NetJ2_12: R101.2 ; port SR-PWM-D
NetR95_1: R95.1 U12.2(A1)
NetR96_1: R96.1 U12.15(B1)
NetR97_1: R97.1 U12.3(A2)
NetR98_1: R98.1 U12.14(B2)
NetR99_1: R99.1 U12.4(A3)
NetR100_1: R100.1 U12.13(B3)
NetR101_1: R101.1 U12.5(A4)
NetR102_1: R102.1 U12.12(B4)

Not connected (* = marked no-connect by the designer): U12 6(A5)* 7(A6)* 10(B6)* 11(B5)*

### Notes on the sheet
- PCB Ver.: 01
- BOM Ver.: A
- Prepared by:
- Approved by:
- .
- Frank Wei
- Kevin Xie

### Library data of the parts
C129-C132 = CAP NP
R92-R102 = RESISTOR
U12 = Si8661_3

## Sheet P4 DCDC Primary Gate Dr.SchDoc
size 594 x 420 mm
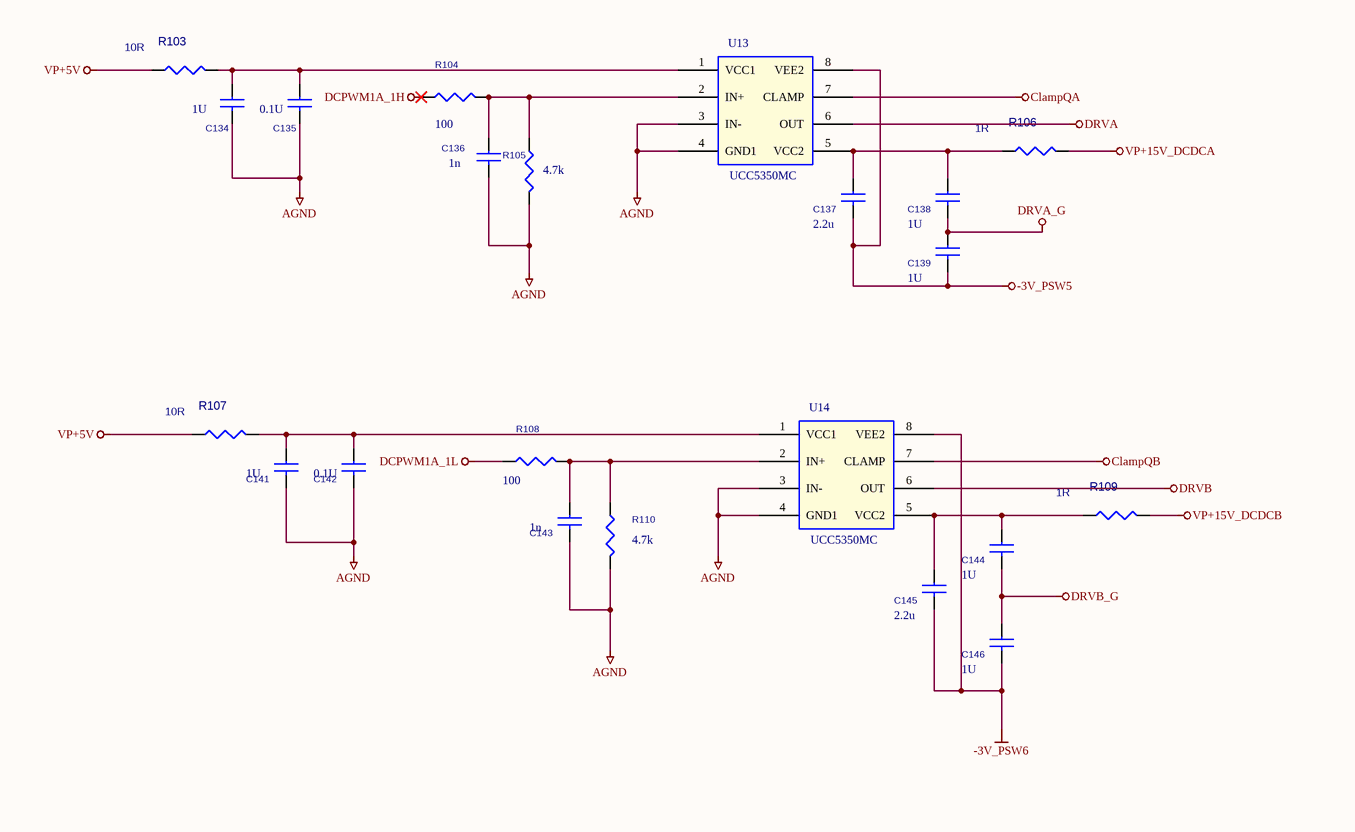
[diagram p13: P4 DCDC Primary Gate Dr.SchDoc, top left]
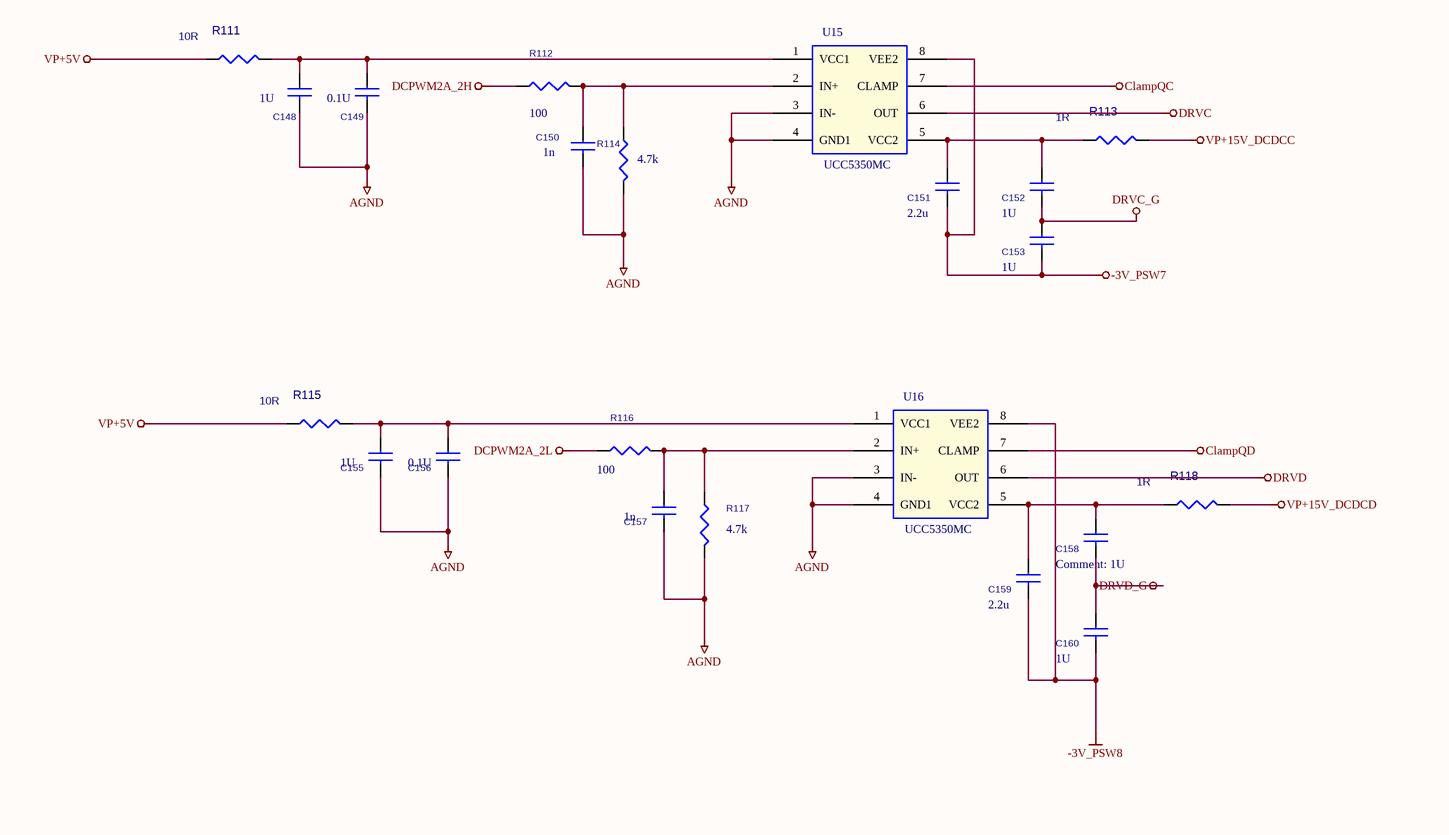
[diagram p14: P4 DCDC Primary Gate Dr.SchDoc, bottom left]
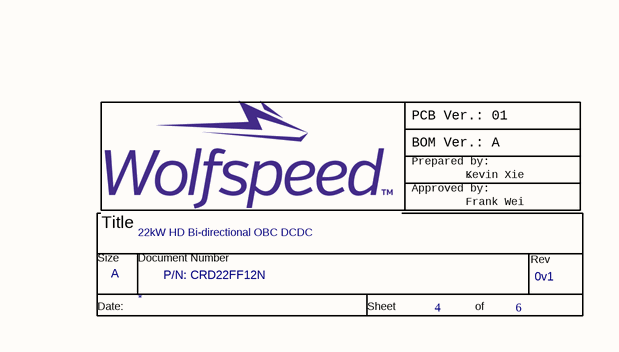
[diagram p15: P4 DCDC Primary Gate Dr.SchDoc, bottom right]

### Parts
(Parts that share a designator on the sheet are numbered #1, #2 ... from top to bottom, then left to right.)
*#4  Page Count: 6  Page Number: 4  Page Size: A  Title: 22kW HD Bi-directional OBC DCDC  RevCode: 0v1  Doc: P/N: CRD22FF12N  (hidden comment: TitleBlock0_cree_power)  (graphical)
C134  1U  [C0603]
C135  0.1U  [C0603]
C136  1n  [C0603]
C137  2.2u  [C0805]
C138  1U  [C0603]
C139  1U  [C0603]
C141  1U  [C0603]
C142  0.1U  [C0603]
C143  1n  [C0603]
C144  1U  [C0603]
C145  2.2u  [C0805]
C146  1U  [C0603]
C148  1U  [C0603]
C149  0.1U  [C0603]
C150  1n  [C0603]
C151  2.2u  [C0805]
C152  1U  [C0603]
C153  1U  [C0603]
C155  1U  [C0603]
C156  0.1U  [C0603]
C157  1n  [C0603]
C158  1U  [C0603]
C159  2.2u  [C0805]
C160  1U  [C0603]
R103  10R  [R0603]
R104  100  [R0603]
R105  4.7k  [R0603]
R106  1R  [R0805]
R107  10R  [R0603]
R108  100  [R0603]
R109  1R  [R0805]
R110  4.7k  [R0603]
R111  10R  [R0603]
R112  100  [R0603]
R113  1R  [R0805]
R114  4.7k  [R0603]
R115  10R  [R0603]
R116  100  [R0603]
R117  4.7k  [R0603]
R118  1R  [R0805]
U13  UCC5350MC  [SOIC8_DWV]
U14  UCC5350MC  [SOIC8_DWV]
U15  UCC5350MC  [SOIC8_DWV]
U16  UCC5350MC  [SOIC8_DWV]

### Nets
-3V_PSW5: C137.2 C139.2 U13.8(VEE2)
-3V_PSW6: C145.2 C146.2 U14.8(VEE2)
-3V_PSW7: C151.2 C153.2 U15.8(VEE2)
-3V_PSW8: C159.2 C160.2 U16.8(VEE2)
AGND: C134.2 C135.2 C136.2 C141.2 C142.2 C143.2 C148.2 C149.2 C150.2 C155.2 C156.2 C157.2 R105.2 R110.2 R114.2 R117.2 U13.3(IN-) U13.4(GND1) U14.3(IN-) U14.4(GND1) U15.3(IN-) U15.4(GND1) U16.3(IN-) U16.4(GND1)
ClampQA: U13.7(CLAMP)
ClampQB: U14.7(CLAMP)
ClampQC: U15.7(CLAMP)
ClampQD: U16.7(CLAMP)
DCPWM1A_1H: R104.1
DCPWM1A_1L: R108.1
DCPWM2A_2H: R112.1
DCPWM2A_2L: R116.1
DRVA: U13.6(OUT)
DRVA_G: C138.2 C139.1
DRVB: U14.6(OUT)
DRVB_G: C144.2 C146.1
DRVC: U15.6(OUT)
DRVC_G: C152.2 C153.1
DRVD: U16.6(OUT)
DRVD_G: C158.2 C160.1
VP+5V: R103.1 R107.1 R111.1 R115.1
VP+15V_DCDCA: R106.2
VP+15V_DCDCB: R109.2
VP+15V_DCDCC: R113.2
VP+15V_DCDCD: R118.2
NetC134_1: C134.1 C135.1 R103.2 U13.1(VCC1)
NetC136_1: C136.1 R104.2 R105.1 U13.2(IN+)
NetC137_1: C137.1 C138.1 R106.1 U13.5(VCC2)
NetC141_1: C141.1 C142.1 R107.2 U14.1(VCC1)
NetC143_1: C143.1 R108.2 R110.1 U14.2(IN+)
NetC144_1: C144.1 C145.1 R109.1 U14.5(VCC2)
NetC148_1: C148.1 C149.1 R111.2 U15.1(VCC1)
NetC150_1: C150.1 R112.2 R114.1 U15.2(IN+)
NetC151_1: C151.1 C152.1 R113.1 U15.5(VCC2)
NetC155_1: C155.1 C156.1 R115.2 U16.1(VCC1)
NetC157_1: C157.1 R116.2 R117.1 U16.2(IN+)
NetC158_1: C158.1 C159.1 R118.1 U16.5(VCC2)

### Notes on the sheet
- PCB Ver.: 01
- BOM Ver.: A
- Prepared by:
- Approved by:
- .
- Frank Wei
- Kevin Xie

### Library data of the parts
C134-C139 C141-C146 C148-C153 C155-C160 = CAP NP
R103 R106 R107 R109 R111 R113 R115 R118 = R
R104 R105 R108 R110 R112 R114 R116 R117 = RESISTOR

## Sheet P5 DCDC Secondary Gate .SchDoc
size 594 x 420 mm
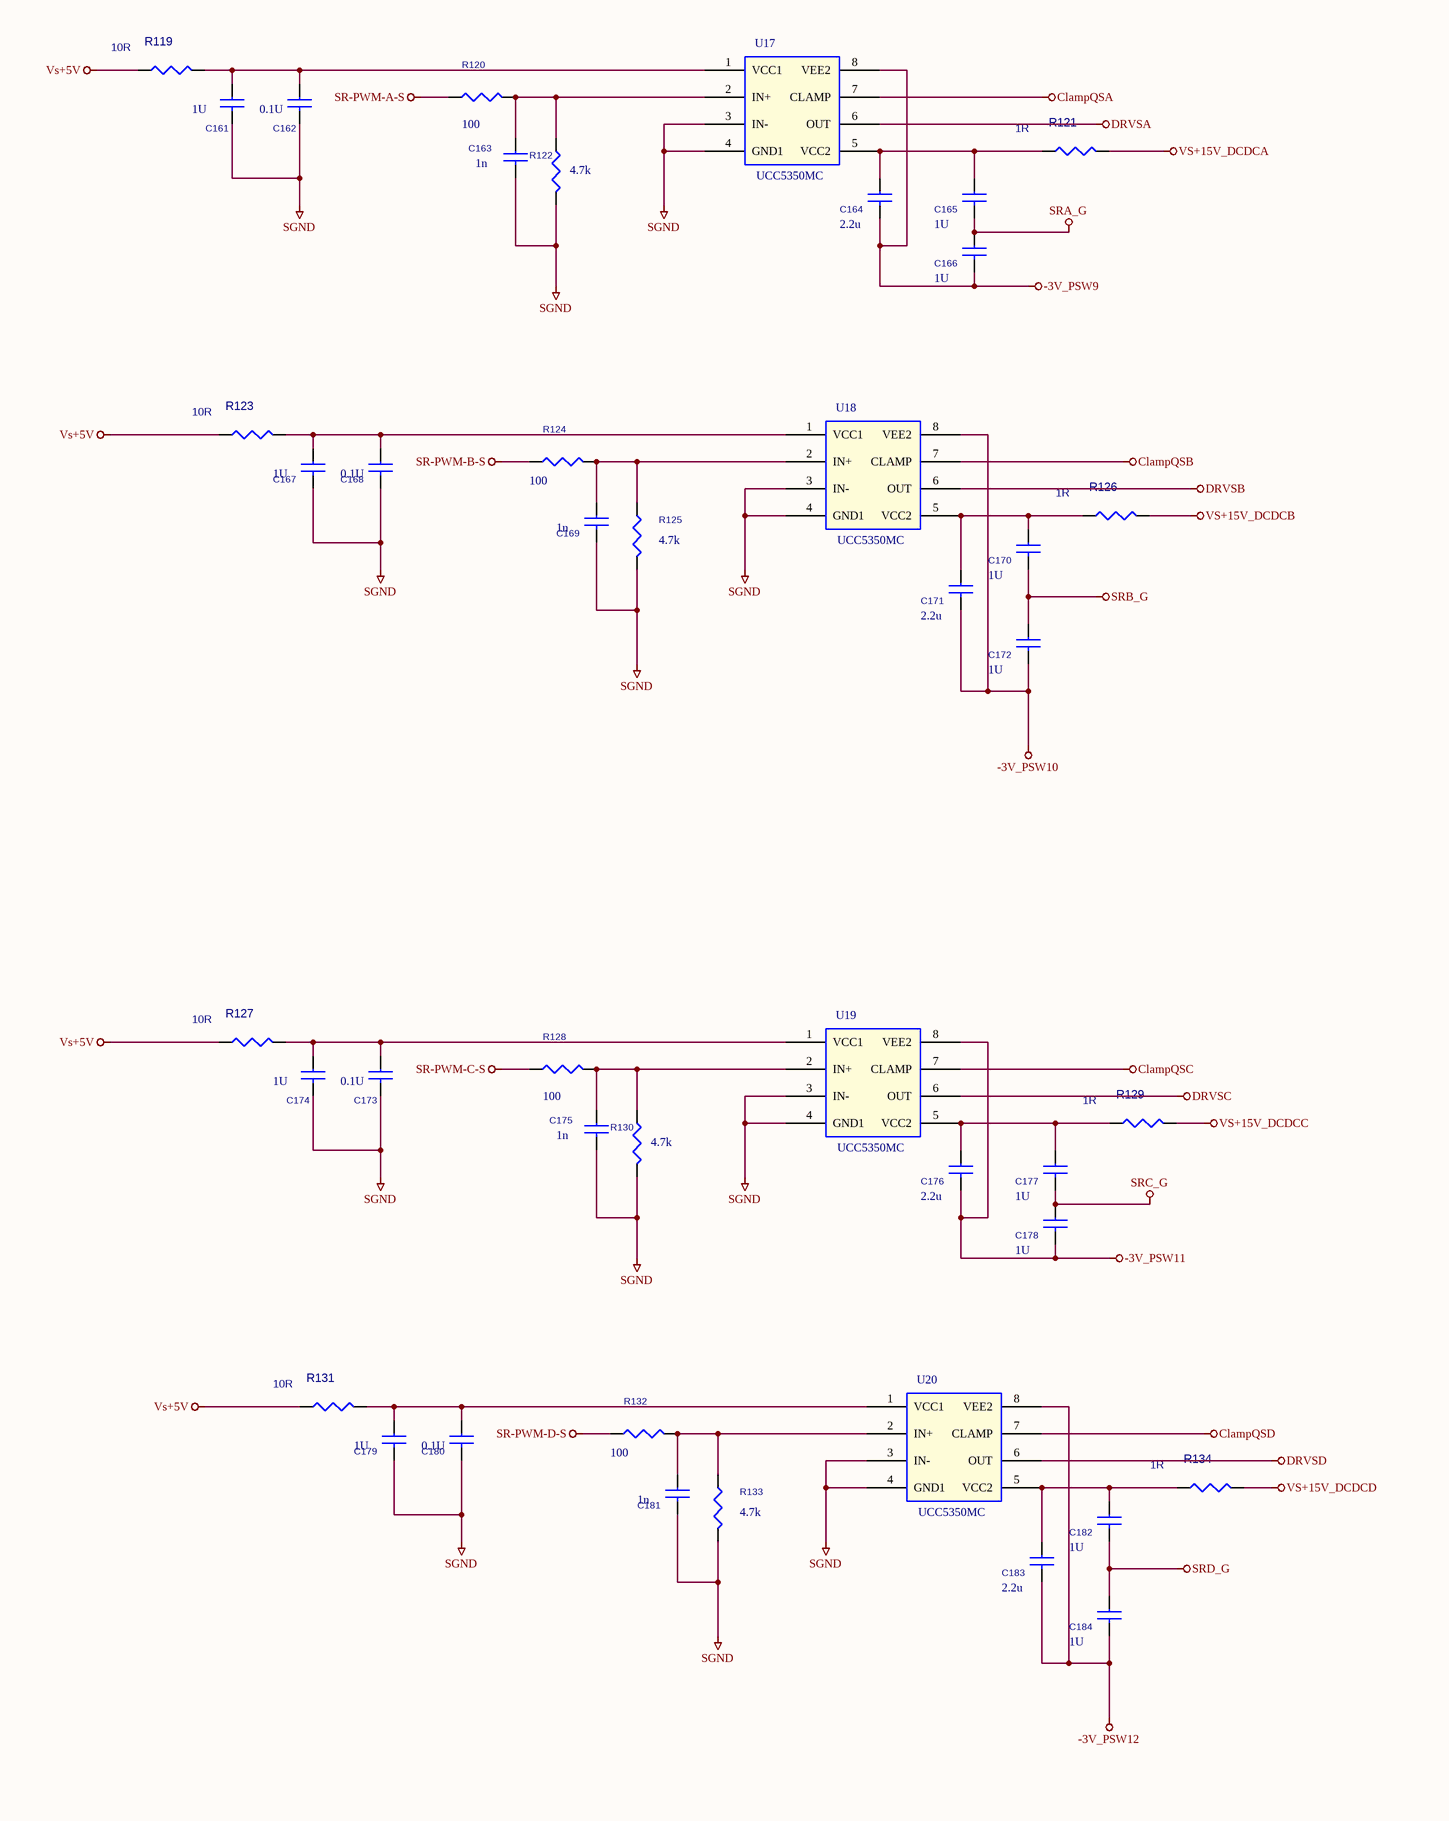
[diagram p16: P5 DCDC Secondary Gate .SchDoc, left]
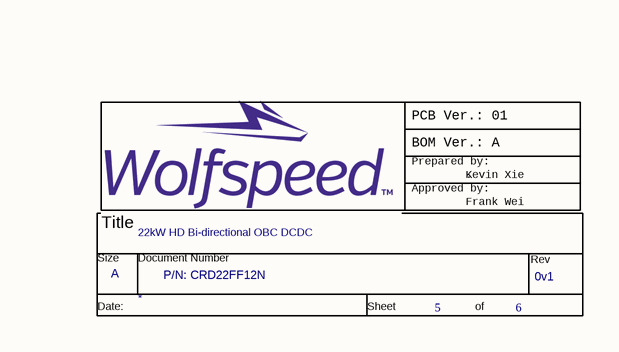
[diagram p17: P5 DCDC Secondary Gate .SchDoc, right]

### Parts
(Parts that share a designator on the sheet are numbered #1, #2 ... from top to bottom, then left to right.)
*#5  Page Count: 6  Page Number: 5  Page Size: A  Title: 22kW HD Bi-directional OBC DCDC  RevCode: 0v1  Doc: P/N: CRD22FF12N  (hidden comment: TitleBlock0_cree_power)  (graphical)
C161  1U  [C0603]
C162  0.1U  [C0603]
C163  1n  [C0603]
C164  2.2u  [C0805]
C165  1U  [C0603]
C166  1U  [C0603]
C167  1U  [C0603]
C168  0.1U  [C0603]
C169  1n  [C0603]
C170  1U  [C0603]
C171  2.2u  [C0805]
C172  1U  [C0603]
C173  0.1U  [C0603]
C174  1U  [C0603]
C175  1n  [C0603]
C176  2.2u  [C0805]
C177  1U  [C0603]
C178  1U  [C0603]
C179  1U  [C0603]
C180  0.1U  [C0603]
C181  1n  [C0603]
C182  1U  [C0603]
C183  2.2u  [C0805]
C184  1U  [C0603]
R119  10R  [R0603]
R120  100  [R0603]
R121  1R  [R0805]
R122  4.7k  [R0603]
R123  10R  [R0603]
R124  100  [R0603]
R125  4.7k  [R0603]
R126  1R  [R0805]
R127  10R  [R0603]
R128  100  [R0603]
R129  1R  [R0805]
R130  4.7k  [R0603]
R131  10R  [R0603]
R132  100  [R0603]
R133  4.7k  [R0603]
R134  1R  [R0805]
U17  UCC5350MC  [SOIC8_DWV]
U18  UCC5350MC  [SOIC8_DWV]
U19  UCC5350MC  [SOIC8_DWV]
U20  UCC5350MC  [SOIC8_DWV]

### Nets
-3V_PSW9: C164.2 C166.2 U17.8(VEE2)
-3V_PSW10: C171.2 C172.2 U18.8(VEE2)
-3V_PSW11: C176.2 C178.2 U19.8(VEE2)
-3V_PSW12: C183.2 C184.2 U20.8(VEE2)
ClampQSA: U17.7(CLAMP)
ClampQSB: U18.7(CLAMP)
ClampQSC: U19.7(CLAMP)
ClampQSD: U20.7(CLAMP)
DRVSA: U17.6(OUT)
DRVSB: U18.6(OUT)
DRVSC: U19.6(OUT)
DRVSD: U20.6(OUT)
SGND: C161.2 C162.2 C163.2 C167.2 C168.2 C169.2 C173.2 C174.2 C175.2 C179.2 C180.2 C181.2 R122.2 R125.2 R130.2 R133.2 U17.3(IN-) U17.4(GND1) U18.3(IN-) U18.4(GND1) U19.3(IN-) U19.4(GND1) U20.3(IN-) U20.4(GND1)
SR-PWM-A-S: R120.1
SR-PWM-B-S: R124.1
SR-PWM-C-S: R128.1
SR-PWM-D-S: R132.1
SRA_G: C165.2 C166.1
SRB_G: C170.2 C172.1
SRC_G: C177.2 C178.1
SRD_G: C182.2 C184.1
Vs+5V: R119.1 R123.1 R127.1 R131.1
VS+15V_DCDCA: R121.2
VS+15V_DCDCB: R126.2
VS+15V_DCDCC: R129.2
VS+15V_DCDCD: R134.2
NetC161_1: C161.1 C162.1 R119.2 U17.1(VCC1)
NetC163_1: C163.1 R120.2 R122.1 U17.2(IN+)
NetC164_1: C164.1 C165.1 R121.1 U17.5(VCC2)
NetC167_1: C167.1 C168.1 R123.2 U18.1(VCC1)
NetC169_1: C169.1 R124.2 R125.1 U18.2(IN+)
NetC170_1: C170.1 C171.1 R126.1 U18.5(VCC2)
NetC173_1: C173.1 C174.1 R127.2 U19.1(VCC1)
NetC175_1: C175.1 R128.2 R130.1 U19.2(IN+)
NetC176_1: C176.1 C177.1 R129.1 U19.5(VCC2)
NetC179_1: C179.1 C180.1 R131.2 U20.1(VCC1)
NetC181_1: C181.1 R132.2 R133.1 U20.2(IN+)
NetC182_1: C182.1 C183.1 R134.1 U20.5(VCC2)

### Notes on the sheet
- PCB Ver.: 01
- BOM Ver.: A
- Prepared by:
- Approved by:
- .
- Frank Wei
- Kevin Xie

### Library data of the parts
C161-C184 = CAP NP
R119 R121 R123 R126 R127 R129 R131 R134 = R
R120 R122 R124 R125 R128 R130 R132 R133 = RESISTOR

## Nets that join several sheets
-3V_PSW5: P2 Bias POWER SUPPLY (C85.2 C86.2 U4.5), P4 DCDC Primary Gate Dr (C137.2 C139.2 U13.8)
-3V_PSW6: P2 Bias POWER SUPPLY (C89.2 C91.2 U5.5), P4 DCDC Primary Gate Dr (C145.2 C146.2 U14.8)
-3V_PSW7: P2 Bias POWER SUPPLY (C87.2 C88.2 U7.5), P4 DCDC Primary Gate Dr (C151.2 C153.2 U15.8)
-3V_PSW8: P2 Bias POWER SUPPLY (C90.2 C92.2 U6.5), P4 DCDC Primary Gate Dr (C159.2 C160.2 U16.8)
-3V_PSW9: P2 Bias POWER SUPPLY (C113.2 C114.2 U8.5), P5 DCDC Secondary Gate  (C164.2 C166.2 U17.8)
-3V_PSW10: P2 Bias POWER SUPPLY (C123.2 C124.2 U9.5), P5 DCDC Secondary Gate  (C171.2 C172.2 U18.8)
-3V_PSW11: P2 Bias POWER SUPPLY (C125.2 C126.2 U10.5), P5 DCDC Secondary Gate  (C176.2 C178.2 U19.8)
-3V_PSW12: P2 Bias POWER SUPPLY (C127.2 C128.2 U11.5), P5 DCDC Secondary Gate  (C183.2 C184.2 U20.8)
AGND: P1 Main DCDC (6 pins), P2 Bias POWER SUPPLY (36 pins), P3 Isolation Interface (C130.2 C131.1 U12.8), P4 DCDC Primary Gate Dr (24 pins)
ClampQA: P1 Main DCDC (5 pins), P4 DCDC Primary Gate Dr (U13.7)
ClampQB: P1 Main DCDC (5 pins), P4 DCDC Primary Gate Dr (U14.7)
ClampQC: P1 Main DCDC (5 pins), P4 DCDC Primary Gate Dr (U15.7)
ClampQD: P1 Main DCDC (5 pins), P4 DCDC Primary Gate Dr (U16.7)
ClampQSA: P1 Main DCDC (C22.1 Q7.4 R58.1 R62.2), P5 DCDC Secondary Gate  (U17.7)
ClampQSB: P1 Main DCDC (C42.1 Q17.4 R72.1 R75.2), P5 DCDC Secondary Gate  (U18.7)
ClampQSC: P1 Main DCDC (C23.1 Q16.4 R59.2 R64.2), P5 DCDC Secondary Gate  (U19.7)
ClampQSD: P1 Main DCDC (C43.1 Q18.4 R73.2 R76.2), P5 DCDC Secondary Gate  (U20.7)
CS: P1 Main DCDC (D4.2 D6.2 D11.2 D12.2), P2 Bias POWER SUPPLY (J2.1)
CS_Pri: P1 Main DCDC (D3.2 D5.2 D9.2 D10.2), P2 Bias POWER SUPPLY (J1.18)
CS_RTN: P1 Main DCDC (D4.1 D6.1 D11.1 D12.1), P2 Bias POWER SUPPLY (J2.3)
CS_RTN_Pri: P1 Main DCDC (D3.1 D5.1 D9.1 D10.1), P2 Bias POWER SUPPLY (J1.20)
DC-OV: P1 Main DCDC (R70.1), P2 Bias POWER SUPPLY (J1.22)
DC_FB: P1 Main DCDC (R69.1), P2 Bias POWER SUPPLY (J1.24)
DCPWM1A_1H: P2 Bias POWER SUPPLY (J2.4), P4 DCDC Primary Gate Dr (R104.1)
DCPWM1A_1L: P2 Bias POWER SUPPLY (J2.2), P4 DCDC Primary Gate Dr (R108.1)
DCPWM2A_2H: P2 Bias POWER SUPPLY (J2.7), P4 DCDC Primary Gate Dr (R112.1)
DCPWM2A_2L: P2 Bias POWER SUPPLY (J2.5), P4 DCDC Primary Gate Dr (R116.1)
DRVA: P1 Main DCDC (D1.2 R4.2), P4 DCDC Primary Gate Dr (U13.6)
DRVA_G: P1 Main DCDC (C5.2 Q1.3 R8.1), P2 Bias POWER SUPPLY (6 pins), P4 DCDC Primary Gate Dr (C138.2 C139.1)
DRVB: P1 Main DCDC (D7.2 R19.2), P4 DCDC Primary Gate Dr (U14.6)
DRVB_G: P1 Main DCDC (C14.2 Q3.3 R21.1), P2 Bias POWER SUPPLY (6 pins), P4 DCDC Primary Gate Dr (C144.2 C146.1)
DRVC: P1 Main DCDC (D2.2 R5.1), P4 DCDC Primary Gate Dr (U15.6)
DRVC_G: P1 Main DCDC (C4.2 Q2.3 R9.1), P2 Bias POWER SUPPLY (6 pins), P4 DCDC Primary Gate Dr (C152.2 C153.1)
DRVD: P1 Main DCDC (D8.2 R20.1), P4 DCDC Primary Gate Dr (U16.6)
DRVD_G: P1 Main DCDC (C15.2 Q4.3 R22.1), P2 Bias POWER SUPPLY (6 pins), P4 DCDC Primary Gate Dr (C158.2 C160.1)
DRVSA: P1 Main DCDC (R58.2), P5 DCDC Secondary Gate  (U17.6)
DRVSB: P1 Main DCDC (R72.2), P5 DCDC Secondary Gate  (U18.6)
DRVSC: P1 Main DCDC (R59.1), P5 DCDC Secondary Gate  (U19.6)
DRVSD: P1 Main DCDC (R73.1), P5 DCDC Secondary Gate  (U20.6)
SGND: P2 Bias POWER SUPPLY (28 pins), P3 Isolation Interface (C129.2 C132.1 U12.9), P5 DCDC Secondary Gate  (24 pins)
SR-PWM-A-S: P3 Isolation Interface (R96.2), P5 DCDC Secondary Gate  (R120.1)
SR-PWM-B-S: P3 Isolation Interface (R98.2), P5 DCDC Secondary Gate  (R124.1)
SR-PWM-C-S: P3 Isolation Interface (R100.2), P5 DCDC Secondary Gate  (R128.1)
SR-PWM-D-S: P3 Isolation Interface (R102.2), P5 DCDC Secondary Gate  (R132.1)
SRA_G: P1 Main DCDC (C22.2 Q7.3 R62.1), P2 Bias POWER SUPPLY (6 pins), P5 DCDC Secondary Gate  (C165.2 C166.1)
SRB_G: P1 Main DCDC (C42.2 Q17.3 R75.1), P2 Bias POWER SUPPLY (6 pins), P5 DCDC Secondary Gate  (C170.2 C172.1)
SRC_G: P1 Main DCDC (C23.2 Q16.3 R64.1), P2 Bias POWER SUPPLY (6 pins), P5 DCDC Secondary Gate  (C177.2 C178.1)
SRD_G: P1 Main DCDC (C43.2 Q18.3 R76.1), P2 Bias POWER SUPPLY (6 pins), P5 DCDC Secondary Gate  (C182.2 C184.1)
VO1+: P1 Main DCDC (R65.2), P2 Bias POWER SUPPLY (J3.1)
VO2+: P1 Main DCDC (R66.2), P2 Bias POWER SUPPLY (J3.3)
VP3.3D: P1 Main DCDC (R38.1), P2 Bias POWER SUPPLY (J1.6)
VP+5V: P2 Bias POWER SUPPLY (6 pins), P3 Isolation Interface (R92.1), P4 DCDC Primary Gate Dr (R103.1 R107.1 R111.1 R115.1)
VP+15V_DCDCA: P2 Bias POWER SUPPLY (C56.1 C57.1 C58.1 U4.7), P4 DCDC Primary Gate Dr (R106.2)
VP+15V_DCDCB: P2 Bias POWER SUPPLY (C59.1 C60.1 C68.1 U5.7), P4 DCDC Primary Gate Dr (R109.2)
VP+15V_DCDCC: P2 Bias POWER SUPPLY (C61.1 C62.1 C69.1 U7.7), P4 DCDC Primary Gate Dr (R113.2)
VP+15V_DCDCD: P2 Bias POWER SUPPLY (C64.1 C65.1 C72.1 U6.7), P4 DCDC Primary Gate Dr (R118.2)
Vs+5V: P2 Bias POWER SUPPLY (5 pins), P3 Isolation Interface (C129.1 R93.2), P5 DCDC Secondary Gate  (R119.1 R123.1 R127.1 R131.1)
VS+15V_DCDCA: P2 Bias POWER SUPPLY (C93.1 C94.1 C95.1 U8.7), P5 DCDC Secondary Gate  (R121.2)
VS+15V_DCDCB: P2 Bias POWER SUPPLY (C97.1 C99.1 C102.1 U9.7), P5 DCDC Secondary Gate  (R126.2)
VS+15V_DCDCC: P2 Bias POWER SUPPLY (C100.1 C104.1 C105.1 U10.7), P5 DCDC Secondary Gate  (R129.2)
VS+15V_DCDCD: P2 Bias POWER SUPPLY (C106.1 C107.1 C117.1 U11.7), P5 DCDC Secondary Gate  (R134.2)
NetJ1_14: P1 Main DCDC (U1.12), P2 Bias POWER SUPPLY (J1.14)
NetJ1_16: P1 Main DCDC (R40.2 U1.13), P2 Bias POWER SUPPLY (J1.16)
NetJ2_9: P2 Bias POWER SUPPLY (J2.9), P3 Isolation Interface (R95.2)
NetJ2_10: P2 Bias POWER SUPPLY (J2.10), P3 Isolation Interface (R97.2)
NetJ2_11: P2 Bias POWER SUPPLY (J2.11), P3 Isolation Interface (R99.2)
NetJ2_12: P2 Bias POWER SUPPLY (J2.12), P3 Isolation Interface (R101.2)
